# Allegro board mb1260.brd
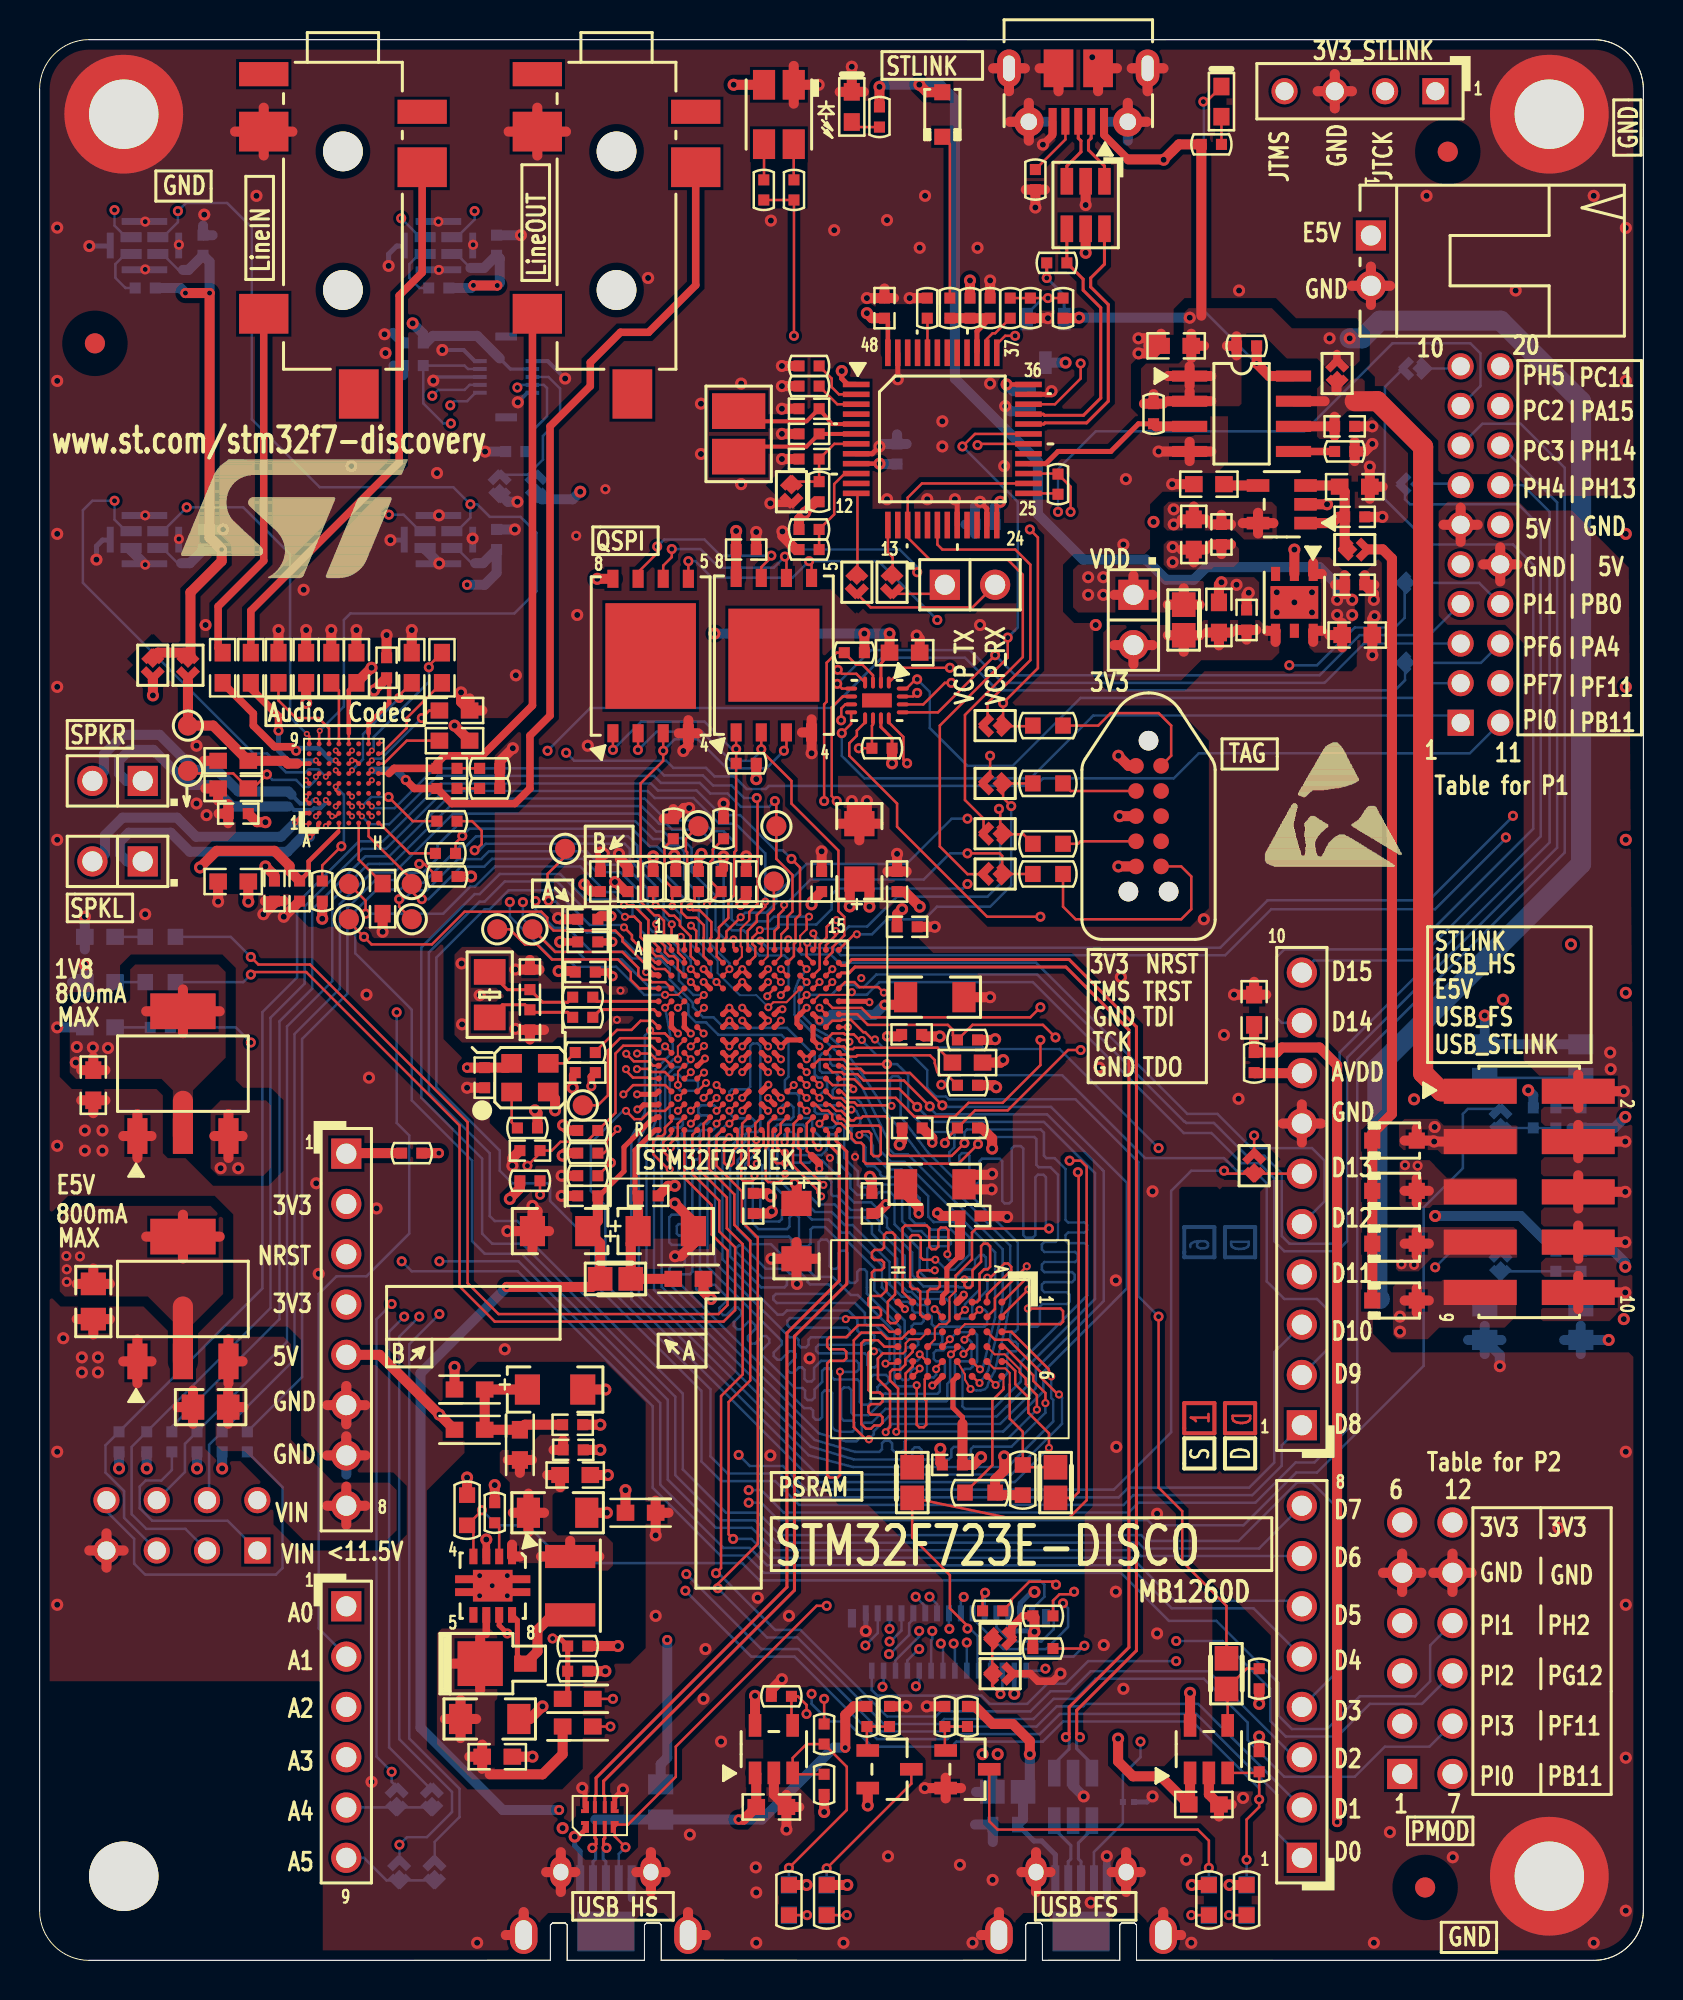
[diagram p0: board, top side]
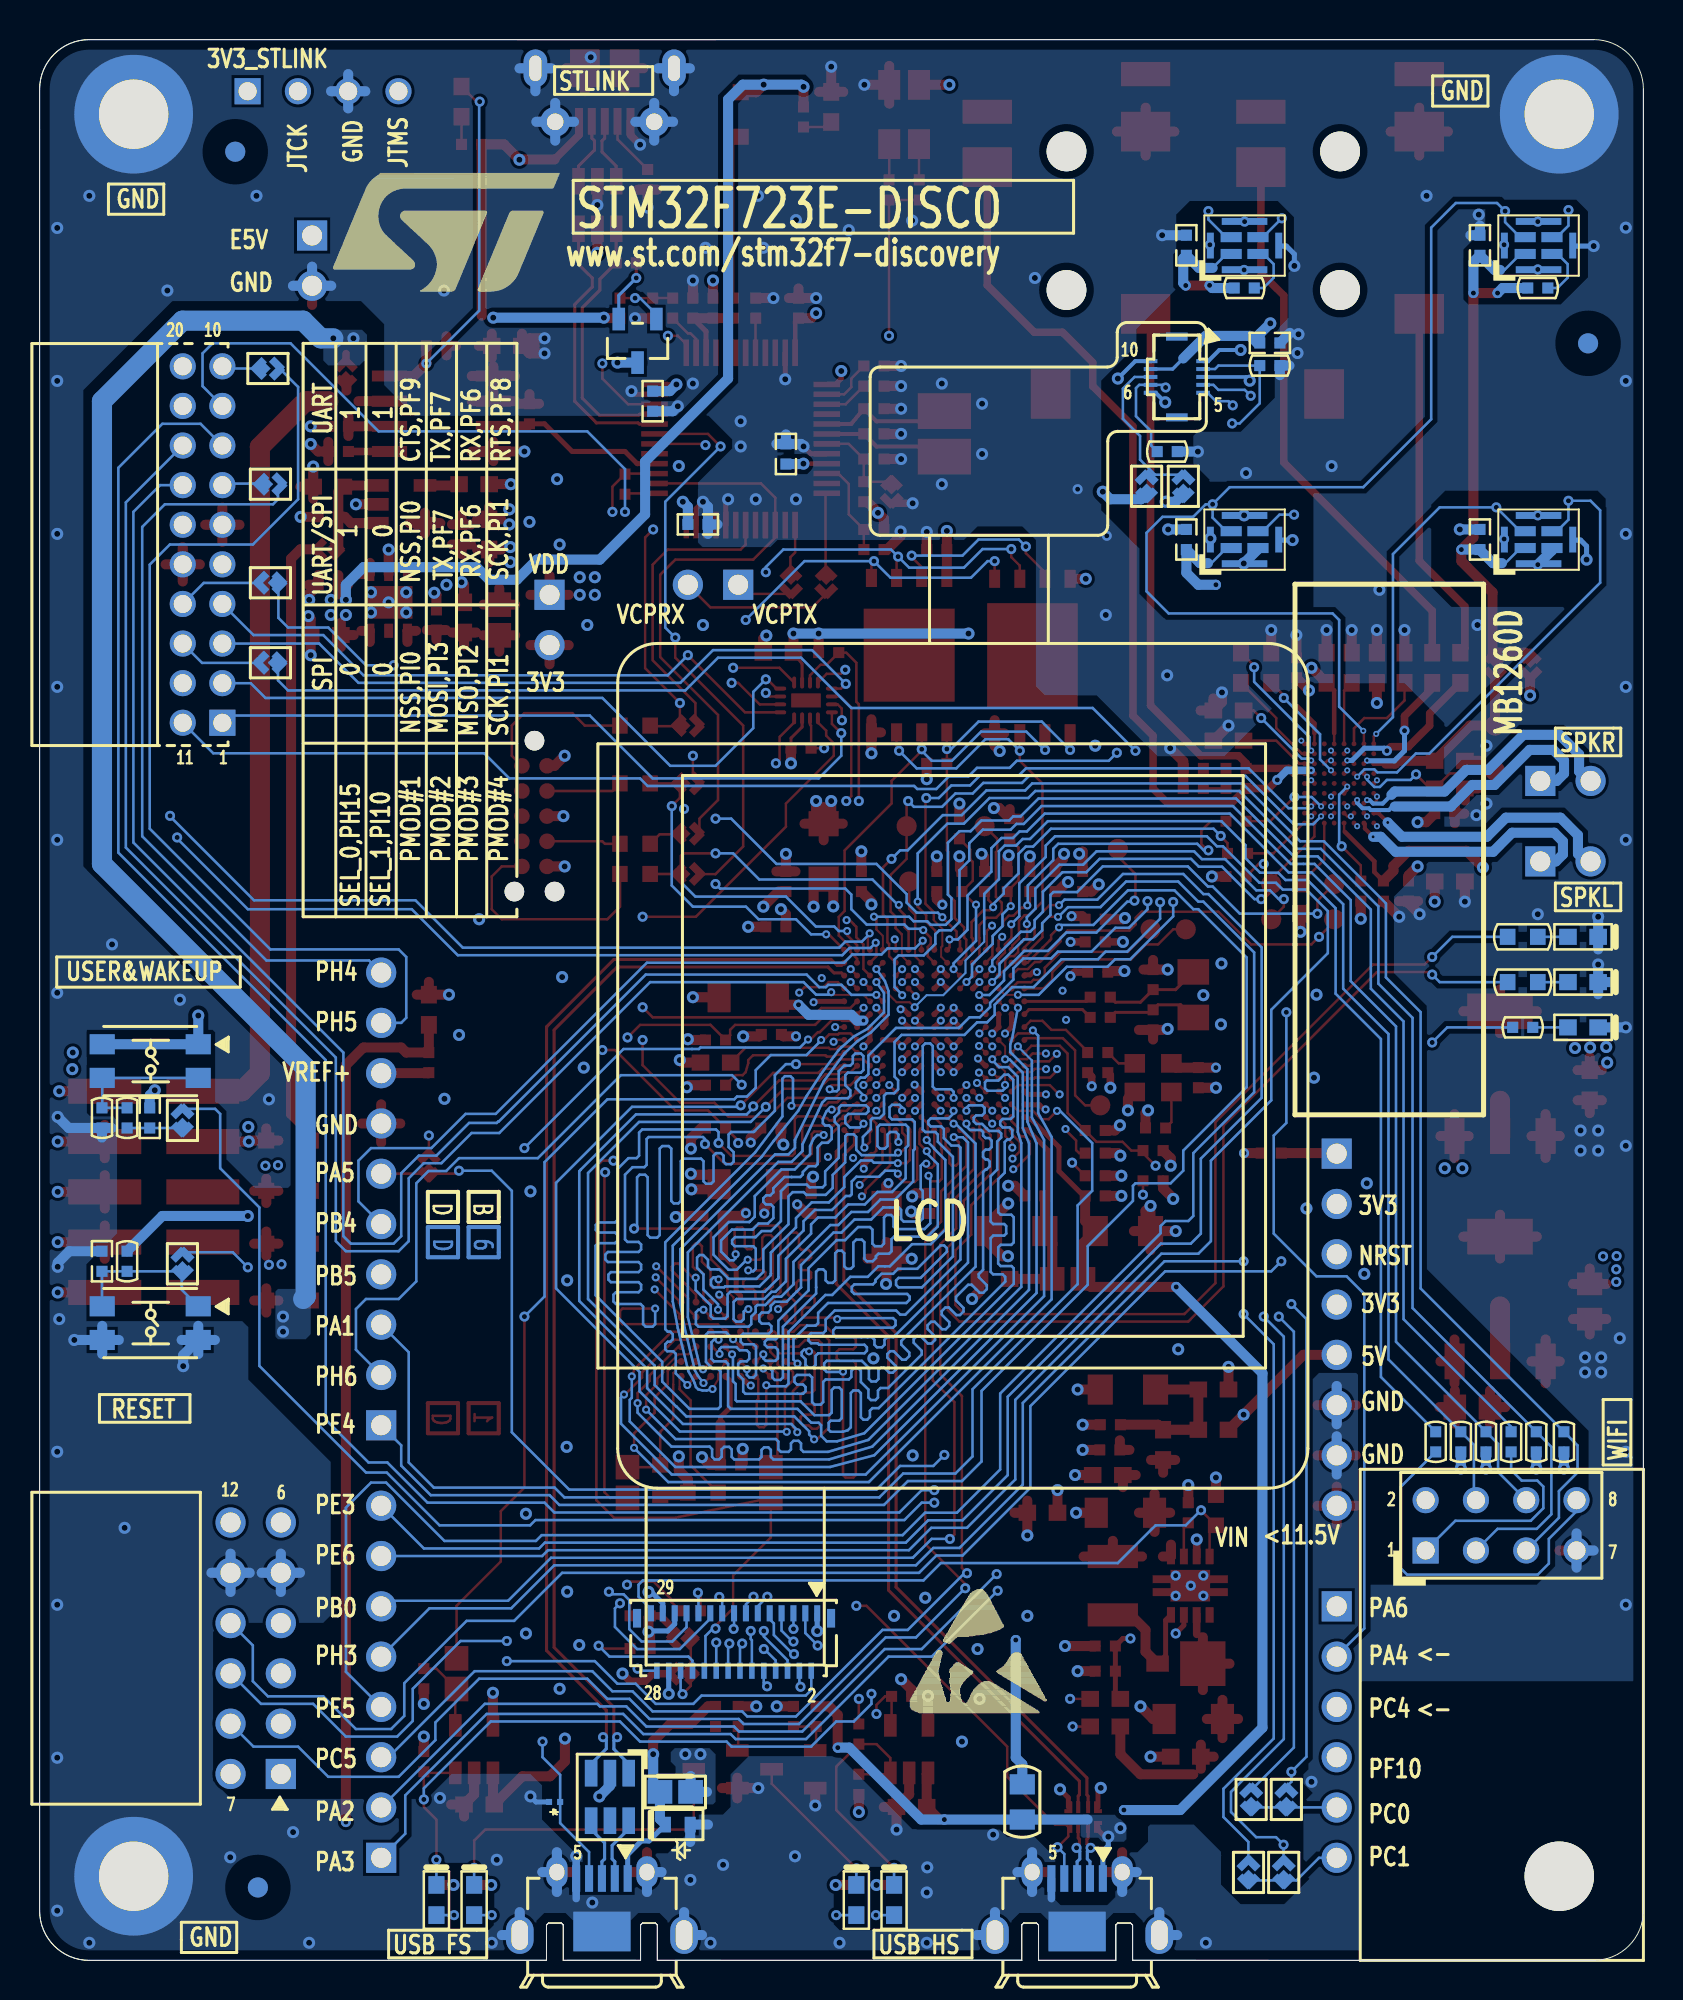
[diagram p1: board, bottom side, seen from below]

Outline 81 x 97 mm; copper layers: TOP, L2_GND, L3_VCC, L4_SIG, L5_GND, BOTTOM. Coordinates in mm from the lower left corner of the outline.
Outline path: 0,94.49 0,90.31 ; 0,94.49 arc(0.74,96.26) 2.51,97 ; 0,94.49 0,90.31 ; 0,90.31 0,2.51 ; 0,90.31 0,2.51 ; 2.51,97 78.49,97 ; 2.51,97 78.49,97 ; 0,2.51 arc(0.74,0.74) 2.51,0 ; 78.49,97 arc(80.27,96.26) 81,94.49 ; 78.49,97 arc(80.27,96.26) 81,94.49 ; 2.51,0 25.8,0 ; 2.51,0 25.8,0 ; 25.8,0 18.95,0 ; 25.8,0 25.8,1.79 ; 25.8,0 25.8,1.79 ; 25.8,1.79 25.9,1.89 ; 25.8,1.79 25.9,1.89 ; 25.9,1.89 26.55,1.89 ; 25.9,1.89 26.55,1.89 ; 26.55,1.89 26.65,1.79 ; 26.55,1.89 26.65,1.79 ; 26.65,1.79 26.65,0 ; 26.65,1.79 26.65,0 ; 26.65,0 30.55,0 ; 26.65,0 30.55,0 ; 30.55,0 30.55,1.79 ; 30.55,0 30.55,1.79 ; 30.55,1.79 30.65,1.89 ; 30.55,1.79 30.65,1.89 ; 30.65,1.89 31.3,1.89 ; 30.65,1.89 31.3,1.89 ; 31.3,1.89 31.4,1.79 ; 31.3,1.89 31.4,1.79 ; 31.4,1.79 31.4,0 ; 31.4,1.79 31.4,0 ; 31.4,0 34.57,0 ; 31.4,0 48.9,0 ; 31.4,0 49.8,0 ; 31.4,0 49.8,0 ; 49.8,0 49.8,1.79 ; 49.8,0 49.8,1.79 ; 49.8,1.79 49.9,1.89 ; 49.8,1.79 49.9,1.89 ; 49.9,1.89 50.55,1.89 ; 49.9,1.89 50.55,1.89 ; 50.55,1.89 50.65,1.79 ; 50.55,1.89 50.65,1.79 ; 50.65,1.79 50.65,0 ; 50.65,1.79 50.65,0 ; 50.65,0 54.55,0 ; 50.65,0 54.55,0 ; 54.55,0 54.55,1.79 ; 54.55,0 54.55,1.79 ; 50.93,0 54.36,0 ; 54.55,1.79 54.65,1.89 ; 54.55,1.79 54.65,1.89 ; 54.65,1.89 55.3,1.89 ; 54.65,1.89 55.3,1.89 ; 55.3,1.89 55.4,1.79 ; 55.3,1.89 55.4,1.79 ; 55.4,1.79 55.4,0 ; 55.4,1.79 55.4,0 ; 55.4,0 58.57,0 ; 55.4,0 78.49,0 ; 55.4,0 78.49,0 ; 78.49,0 arc(80.27,0.74) 81,2.51 ; 78.49,0 arc(80.27,0.74) 81,2.51 ; 81,94.49 81,92.47 ; 81,94.49 81,92.47 ; 81,92.47 81,2.51 ; 81,92.47 81,2.51

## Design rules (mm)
net group 5V_USB_HS: nets 5V_USB_HS USB_OTGHS_VBUS
net group ARD_D5: nets ARD_D5 STMOD+_TIM3_CH3
net group ARD_D14: nets ARD_D14 STMOD+_I2C2_SDA
net group DIFFPAIR1: nets NETCN7_1 NETCN7_2
net group DIFFPAIR2: nets NETCN10_1 NETCN10_2
net group LCD-RS_A0: nets LCD-RS_A0 PSRAM_A0
net group LCD_PSRAM_NWE: nets LCD_PSRAM_NWE NETR64_2
net group NETB1_2: nets NETB1_2 NETC86_2
net group NETC9_2: nets NETC9_2 NETD2_2
net group NETC18_1: nets NETC18_1 NETC18_2
net group NETC25_1: nets NETC25_1 NETC25_2
net group NETC27_1: nets NETC27_1 NETC27_2
net group NETC30_1: nets NETC30_1 NETC30_2
net group NETC32_1: nets NETC32_1 NETC32_2
net group NETC48_2: nets NETC48_2 PC14-OSC32_IN
net group NETC51_2: nets NETC51_2 PC15-OSC32_OUT
net group NETCN14_1: nets NETCN14_1 WIFI_RX
net group NETCN14_8: nets NETCN14_8 WIFI_TX
net group NETLD5_1: nets NETLD5_1 SYS_LD_USER1
net group NETLD6_1: nets NETLD6_1 SYS_LD_USER2
net group NETLD7_2: nets NETLD7_2 USB_OTGHS_OVCR
net group NETR10_1: nets NETR10_1 USB_STLK_P
net group NETR35_2: nets NETR35_2 SAI2_I2C1_SDA
net group NETR39_2: nets NETR39_2 SAI2_I2C1_SCL
net group NETR63_1: nets NETR63_1 PSRAM_NE1
net group NETR72_2: nets NETR72_2 USB_OTGFS_PPWR_EN
net group NETR76_2: nets NETR76_2 USB_OTGFS_VBUS
net group OSC_25M: nets OSC_25M PH0-OSCIN
net group STLINK_RX: nets STLINK_RX VCP_TX
net group STLINK_TX: nets STLINK_TX VCP_RX
net group SYS_STLINK_JTMS: nets SYS_STLINK_JTMS TAG_SWDIO
net group T_JTMS: nets T_JTMS T_SWDIO_IN
net group USB_OTGFS: nets USB_OTGFS_N USB_OTGFS_P
net group USB_OTGFS_CN: nets USB_OTGFS_CN_N USB_OTGFS_CN_P
net group USB_OTGHS: nets USB_OTGHS_N USB_OTGHS_P
net group USB_OTGHS_CN: nets USB_OTGHS_CN_N USB_OTGHS_CN_P
net group USB_STLK_CN: nets USB_STLK_CN_N USB_STLK_CN_P
net group 3V3_ST_LINK: nets AIN_1 NETD1_2 PWR_EXT STM_RST
net group 5V: nets NETLD2_1
net group 5V_ST_LINK: nets NETLD3_1 NETLD3_2 NETR7_1 PWR_ENN USB_RENUMN
net group ARD_A5: nets ARD_A5 ARD_D15 NETCN15_6
net group ARD_D13: nets ARD_D13 NETLD1_1 NETR12_2
net group BLGND: nets LEDK NETC67_1 NETL7_2 NETR67_2
net group DATA: nets NETR19_2
net group DIFFPAIR0: nets USB_STLK_N
net group DMIC_VDD: nets DMIC_VDD NETR85_1 NETR86_1
net group E5V: nets NETCN12_1
net group LED_STLINK: nets LED_STLINK NETLD4_2 NETLD4_3
net group NETB2_1: nets NETB2_1 NRST TAG_NRST
net group NETCN11_8: nets NETCN11_8 VDDA VREF+
net group SYS_STLINK_JTCK: nets SYS_STLINK_JTCK T_JTCK TAG_SWCLK
net group SYS_STLINK_JTDO-SWO: nets SYS_STLINK_JTDO-SWO T_SWO TAG_SWO

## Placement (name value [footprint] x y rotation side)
B1  SW-PUSH-CMS_EVQP2_BLUE  [TACT_4SM_3R5X5R5]  75.41 45.42 90 bottom
B2  SW-PUSH-CMS_EVQP2_BLACK  [TACT_4SM_3R5X5R5]  75.41 32.18 90 bottom
C1  100nF  [0402C]  42.67 83.44 90 top
C2  100nF  [0402C]  18.87 81.68 180 bottom
C3  1uF  [0603C]  57.4 81.53 0 top
C4  10pF  [0402C]  38.86 78.36 0 top
C5  100nF  [0402C]  65.91 77.47 180 top
C6  10pF  [0402C]  38.86 77.09 0 top
C7  100nF  [0402C]  38.86 75.82 0 top
C8  10nF_X7R_10%_0603  [0603C]  59.05 74.55 0 top
C9  1uF  [0603C]  66.42 74.42 180 top
C10  100nF  [0402C]  66.42 72.9 180 top
C11  1uF  [0603C]  58.29 72.01 90 top
C12  100nF  [0402C]  59.69 72.01 90 top
C13  100nF  [0402C]  35.69 71.25 180 top
C14  100nF  [0402C]  66.42 69.47 180 top
C15  1uF  [0603C]  59.56 67.82 270 top
C16  100nF  [0402C]  60.96 67.69 270 top
C17  1uF  [0603C]  66.55 66.93 180 top
C18  1uF  [0603C]  10.67 65.28 90 top
C19  4.7uF  [0603C]  12.06 65.28 270 top
C20  4.7uF  [0603C]  13.46 65.28 90 top
C21  4.7uF  [0603C]  14.73 65.28 90 top
C22  4.7uF  [0603C]  16 65.28 90 top
C23  100nF  [0402C]  17.53 65.28 90 top
C24  1uF  [0603C]  18.8 65.28 90 top
C25  2.2uF_X5R_10%_0603  [0603C]  20.32 65.28 90 top
C26  2.2uF_X5R_10%_0603  [0603C]  20.95 63.12 0 top
C27  1uF  [0603C]  9.25 65.28 90 top
C28  2.2uF_X5R_10%_0603  [0603C]  20.95 61.59 0 top
C29  4.7uF  [0603C]  9.78 60.58 0 top
C30  100nF  [0402C]  20.57 60.2 0 top
C31  4.7uF  [0603C]  9.78 59.18 0 top
C32  100nF  [0402C]  20.57 59.18 0 top
C33  100nF  [0402C]  10.03 57.91 180 top
C34  4.7uF  [TAN-A]  41.4 56.01 270 top
C35  1uF  [0603C]  9.78 54.48 0 top
C36  100nF  [0402C]  28.32 54.48 270 top
C37  100nF  [0402C]  29.72 54.48 270 top
C38  100nF  [0402C]  35.69 54.48 270 top
C39  100nF  [0402C]  39.5 54.48 270 top
C40  100nF  [0402C]  43.31 54.48 270 top
C41  100nF  [0402C]  11.86 54 270 top
C42  100nF  [0402C]  13.13 54 270 top
C43  1uF  [0603C]  17.32 53.62 90 top
C44  100nF  [0402C]  27.69 52.58 0 top
C45  100nF  [0402C]  43.81 52.2 180 top
C46  100nF  [0402C]  27.69 51.44 0 top
C47  100nF  [0402C]  27.56 49.91 0 top
C48  4.7pF_NPO_-+0.25pF_0402  [0402C]  24.77 49.53 270 top
C49  2.2uF  [1206C]  45.21 48.64 180 top
C50  1uF  [0603C]  61.34 48.01 270 top
C51  4.7pF_NPO_-+0.25pF_0402  [0402C]  24.77 47.5 90 top
C52  100nF  [0402C]  44.04 46.76 180 top
C53  100nF  [0402C]  27.56 44.83 0 top
C54  2.2uF_X5R_10%_0603  [0603C]  46.86 45.34 0 top
C55  100nF  [0402C]  22.48 44.58 90 top
C56  100nF  [0402C]  44.07 42.04 180 top
C57  10uF  [0603C]  2.71 44.2 90 top
C58  2.2uF  [1206C]  45.21 39.19 180 top
C59  100nF  [0402C]  27.69 38.61 0 top
C60  100nF  [0402C]  30.73 38.61 180 top
C61  100nF  [0402C]  36.04 38.23 90 top
C62  100nF  [0402C]  42.04 38.23 90 top
C63  100nF  [0402C]  46.99 37.59 180 top
C64  1uF  [TAN-A]  26.29 36.83 0 top
C65  1uF  [TAN-A]  31.62 36.83 180 top
C66  4.7uF  [TAN-A]  38.23 36.83 90 top
C67  10uF_POL_10%_TANA  [TAN-A]  26.04 28.83 180 top
C68  10uF  [0805C]  2.71 33.27 90 top
C69  100nF  [0402C]  26.92 27.05 180 top
C70  100nF  [0402C]  26.95 25.78 180 top
C71  100nF  [0402C]  46.1 25.02 0 top
C72  10nF_X7R_10%_0603  [0603C]  27.05 24.51 180 top
C73  4.7uF_X7R_10%_1206  [1206C]  26.16 22.61 180 top
C74  10uF  [0805C]  8.64 27.94 0 top
C75  4.7uF_X7R_10%_1206  [1206C]  22.73 12.19 180 top
C76  10nF_X7R_10%_0603  [0603C]  23.11 10.29 180 top
C77  4.7uF  [0603C]  58.8 7.87 0 top
C78  4.7uF  [0603C]  36.96 7.75 0 top
C79  100nF  [0402C]  23.08 86.61 90 bottom
C80  100nF  [0402C]  8.26 86.61 90 bottom
C81  100nF  [0402C]  50.04 78.74 90 bottom
C82  100nF  [0402C]  43.31 76.07 270 bottom
C83  100nF  [0402C]  47.75 72.52 0 bottom
C84  100nF  [0402C]  23.08 71.75 90 bottom
C85  100nF  [0402C]  8.26 71.75 90 bottom
C86  100nF  [0402C]  75.44 42.55 270 bottom
C87  100nF  [0402C]  77.85 35.31 270 bottom
C92  1uF  [0603C]  43.69 66.04 0 top
C93  100nF  [0402C]  24.77 40.89 0 top
CN1  1050170001  [MICRO_USB_B_105017]  52.46 92.95 180 top
CN2  Header 4  [HDR_1X4_2R54]  70.5 94.39 180 top
CN3  WF25402-06421  [HDR_1X2_2R54_RA_11R35]  67.24 87.11 90 top
CN4  PJ3028B-3_BE_3PINS  [PJ3028B]  15.32 91.35 270 top
CN5  PJ3028B-3_GR_3PINS  [PJ3028B]  29.14 91.35 270 top
CN6  JP2  [SIP2]  45.72 69.47 0 top
CN7  JP2  [SIP2]  5.21 59.56 180 top
CN8  Header M Straight 5x2H TSM  [TSM-105-01-S-DV]  75.23 38.81 270 top
CN9  -  [TC2050-IDC-NL]  56.01 57.78 270 top
CN10  JP2  [SIP2]  5.21 55.5 180 top
CN11  BL 1-10 G  [HDR_1X10_2R54_W]  63.75 27.02 90 top
CN12  BL 1-8 G  [HDR_1X8_2R54_W]  15.49 40.74 270 top
CN13  BL 1-8 G  [HDR_1X8_2R54_W]  63.75 5.18 90 top
CN14  Header F Straight 4x2H  [HDR_2X4_2R54]  11 20.7 180 bottom
CN15  BL 1-6 G  [HDR_1X6_2R54_W]  15.49 17.88 270 top
CN16  DF37NB-10DS-0.4V (5x)  [DF37NB-10DS-0R4V]  23.56 79.96 90 bottom
CN17  FH26-29S-0.3SHW  [FH26-29S-0R3SHW]  45.93 16.08 0 bottom
CN18  475900001  [MOLEX_47590001]  52.6 4.14 180 bottom
CN19  475900001  [MOLEX_47590001]  28.6 4.14 180 bottom
D1  BAT60JFILM  [SOD-323]  45.59 93.22 90 top
D2  BAT60JFILM  [SOD-323]  68.43 33.32 0 top
D3  BAT60JFILM  [SOD-323]  68.43 36.2 0 top
D4  BAT60JFILM  [SOD-323]  68.43 38.86 0 top
D5  BAT60JFILM  [SOD-323]  68.43 41.4 0 top
H1  POSITION HOLE C6D3R5  [HOLE_C6D3R5]  76.25 93.23 0 top
H2  POSITION HOLE C6D3R5  [HOLE_C6D3R5]  4.25 93.23 0 top
H4  POSITION HOLE C6D3R5  [HOLE_C6D3R5]  76.25 4.25 0 top
JP1  JP2  [SIP2]  55.24 68.96 270 top
L1  FCM1608KF-601T03  [0603L]  32.77 34.42 180 top
L2  FCM1608KF-601T03  [0603L]  21.72 28.83 0 top
L3  FCM1608KF-601T03  [0603L]  21.72 26.8 0 top
L4  FCM1608KF-601T03  [0603L]  24.26 26.04 270 top
L5  FCM1608KF-601T03  [0603L]  30.35 22.61 180 top
L6  4.7uH 1A 30%  [1210L]  26.8 18.92 270 top
L7  FCM1608KF-601T03  [0603L]  27.18 13.21 180 top
L8  FCM1608KF-601T03  [0603L]  27.18 11.81 0 top
LD1  LED blue  [0603D]  3.05 47.12 180 bottom
LD2  LED red  [0603D]  41.02 93.6 90 top
LD3  LED red  [0603D]  59.69 93.87 90 top
LD4  LD_BICOLOR_CMS  [LED2_3528]  37.34 93.22 180 top
LD5  LED red  [0603D]  3.05 51.69 180 bottom
LD6  LED green  [0603D]  3.05 49.4 180 bottom
LD7  LED red  [0603D]  37.85 3.05 90 bottom
LD8  LED green  [0603D]  39.75 3.05 90 bottom
LD9  LED green  [0603D]  59.05 3.05 90 bottom
LD10  LED red  [0603D]  60.96 3.05 90 bottom
NOREF  -  []  450.6 -120.4 0 top
NOREF#2  -  []  13.59 -41.66 0 top
NOREF#3  -  []  15.49 17.88 90 top
NOREF#4  -  []  4.62 72.17 90 top
NOREF#5  -  []  2.51 0 90 top
NOREF#6  -  []  4.7 228.5 0 top
NOREF#7  -  []  283.34 118.87 0 top
NOREF#8  -  []  4.25 4.25 90 top
NOREF#9  -  []  -7.62 0 0 top
NOREF#10  -  []  4.25 4.25 0 top
NOREF#11  -  []  322.2 176.15 0 top
NOREF#12  -  [unnamed#2]  71.12 91.34 0 top
NOREF#13  -  [unnamed#2]  2.79 81.66 0 top
NOREF#14  -  []  4.62 87.02 0 top
NOREF#15  -  []  15.49 5.18 0 top
NOREF#16  -  []  63.75 22.96 90 top
NOREF#17  -  [unnamed#2]  69.98 3.68 0 top
NOREF#18  -  []  0 2.51 0 top
NOREF#19  -  [unnamed#2]  4.25 4.25 0 top
NOREF#20  -  []  76.25 4.25 0 top
NOREF#21  -  []  78.49 0 90 top
NOREF#22  Value  []  34.37 45.18 270 bottom
NOREF#23  -  [unnamed#2]  69.98 3.68 180 bottom
NOREF#24  -  [unnamed#2]  71.12 91.34 180 bottom
NOREF#25  -  [unnamed#2]  2.79 81.66 180 bottom
NOREF#26  Value  []  -60.71 -15.54 270 bottom
P1  -  [SQT-110-01-F-D-RA]  72.77 71.5 270 bottom
P2  -  [SSW-106-02-F-D-RA]  68.82 9.41 270 bottom
R1  1K  [0402R]  42.42 93.09 270 top
R2  1K  [0402R]  59.18 91.71 180 top
R3  100K_1%_0402  [0402R]  44.83 83.44 270 top
R4  2K7  [0402R]  45.97 83.44 90 top
R5  0  [0402R]  46.99 83.44 90 top
R6  4K7_1%_0402  [0402R]  48.01 83.44 270 top
R7  100  [0402R]  49.02 83.44 270 top
R8  36K  [0402R]  50.04 83.44 90 top
R9  100K_1%_0402  [0402R]  50.29 89.93 90 top
R10  1K5  [0402R]  51.37 85.72 0 top
R11  10K  [0402R]  51.69 83.44 90 top
R12  680_1%_0402  [0402R]  6.1 47.12 0 bottom
R13  330  [0402R]  36.58 89.41 90 top
R14  330  [0402R]  38.1 89.41 90 top
R15  100K_1%_0402  [0402R]  60.96 81.53 180 top
R16  47K_1%_0402  [0402R]  37.47 13.34 0 top
R17  10K  [0402R]  38.86 80.52 0 top
R18  100K_1%_0402  [0402R]  24.05 76.19 0 bottom
R19  10K  [0402R]  38.86 79.5 0 top
R20  10K  [0402R]  56.26 78.11 90 top
R21  100K_1%_0402  [0402R]  18.87 80.54 0 bottom
R22  2K2  [0402R]  65.91 76.2 0 top
R23  100  [0402R]  51.44 74.55 270 top
R24  100K_1%_0402  [0402R]  39.37 74.17 270 top
R25  4K7_1%_0402  [0402R]  38.86 72.26 0 top
R26  4K7_1%_0402  [0402R]  38.86 71.25 0 top
R27  0_5%_0603  [0603R-GS]  57.78 67.69 270 top
R28  22R  [R0603]  50.93 62.36 180 top
R29  10K  [0402R]  42.55 61.21 180 top
R30  10K  [0402R]  35.69 60.45 0 top
R31  20  [0402R]  22.73 60.2 0 top
R32  22R  [R0603]  50.93 59.44 180 top
R33  20  [0402R]  22.73 59.18 0 top
R35  0  [0402R]  20.57 57.53 180 top
R36  10K  [0402R]  32 57.15 270 top
R37  10K  [0402R]  34.54 57.15 270 top
R38  22R  [R0603]  50.93 56.39 180 top
R39  0  [0402R]  20.5 55.91 180 top
R40  22R  [R0603]  50.93 54.86 180 top
R41  10K  [0402R]  20.57 54.74 180 top
R42  2K7  [0402R]  30.99 54.48 270 top
R43  10K  [0402R]  32.13 54.48 270 top
R44  2K7  [0402R]  33.27 54.48 270 top
R45  10K  [0402R]  34.42 54.48 270 top
R46  10K  [0402R]  14.27 54 270 top
R47  1K_1%_0603  [0603R]  6.1 51.69 180 bottom
R48  510_1%_0603  [0603R]  6.1 49.4 180 bottom
R49  0  [0402R]  27.43 48.64 0 top
R50  0  [0402R]  27.43 47.62 0 top
R51  100  [0402R]  27.56 45.85 0 top
R52  2K7  [0402R]  46.86 46.48 180 top
R53  0  [0402R]  61.34 45.34 90 top
R54  3K  [0402R]  46.86 44.2 0 top
R55  10K  [0402R]  24.64 42.04 180 top
R56  2K7  [0402R]  46.86 42.04 0 top
R57  10K  [0402R]  27.69 41.91 180 top
R58  1K  [0402R]  18.8 40.77 0 top
R59  2K7  [0402R]  24.77 39.37 180 top
R60  2K7  [0402R]  27.69 40.77 180 top
R61  10K  [0402R]  27.69 39.62 0 top
R62  0_5%_0603  [0603R-GS]  29.08 34.42 0 top
R63  10K_1%_0603  [0603R]  49.66 24.26 270 top
R64  0_5%_0603  [0603R-GS]  44.07 24.13 90 top
R65  0_5%_0603  [0603R-GS]  51.31 24.13 90 top
R66  10_1%_0603  [0603R]  21.59 22.73 270 top
R67  100K_1%_0402  [0402R]  22.99 22.61 270 top
R68  100K_1%_0402  [0402R]  50.67 17.4 0 top
R69  100K_1%_0402  [0402R]  27.18 15.88 180 top
R70  100K_1%_0402  [0402R]  50.67 15.75 0 top
R71  100K_1%_0402  [0402R]  27.18 14.61 180 top
R72  0_5%_0603  [0603R-GS]  59.94 14.48 270 top
R73  47K_1%_0402  [0402R]  61.59 14.22 270 top
R74  47K_1%_0402  [0402R]  41.78 12.32 90 top
R75  100K_1%_0402  [0402R]  42.93 12.32 90 top
R76  10K  [0402R]  45.72 12.32 270 top
R77  47K_1%_0402  [0402R]  46.86 12.32 90 top
R78  0  [0402R]  39.62 11.43 90 top
R79  47K_1%_0402  [0402R]  61.59 10.03 90 top
R80  3K3  [0402R]  39.62 8.89 90 top
R81  620_1%_0603  [0603R]  37.85 3.05 270 top
R82  330_1%_0603  [0603R]  39.75 3.05 90 top
R83  330_1%_0603  [0603R]  59.05 3.05 90 top
R84  620_1%_0603  [0603R]  60.96 3.05 90 top
R85  10K  [0402R]  20.16 84.45 0 bottom
R86  10K  [0402R]  5.33 84.45 0 bottom
R89  10K  [0402R]  77.85 42.55 90 bottom
R90  10K  [0402R]  76.58 42.55 90 bottom
R91  10K  [0402R]  76.58 35.31 90 bottom
R92  1K  [0402R]  6.68 26.19 270 bottom
R93  10K  [0402R]  5.41 26.19 90 bottom
R94  10K  [0402R]  9.22 26.19 90 bottom
R95  10K  [0402R]  7.95 26.19 90 bottom
R96  10K  [0402R]  4.01 26.19 90 bottom
R97  1K  [0402R]  10.49 26.19 90 bottom
R98  0_5%_0805  [0805R]  31.37 8 270 bottom
R99  0_5%_0603  [0603R-GS]  48.9 8.51 180 bottom
R100  10K_1%_0603  [0603R]  47.5 23.62 0 top
R101  0  [0402R]  48.13 17.65 180 top
R102  10K  [0402R]  41.15 66.04 0 top
SB1  Solder Bridge ON  [JP2_SMD]  5.71 65.41 90 top
SB2  Solder Bridge OFF  [JP2_SMD]  23.24 74.44 270 bottom
SB3  Solder Bridge OFF  [JP2_SMD]  65.53 80.14 270 top
SB4  Solder Bridge ON  [JP2_SMD]  25.09 74.44 270 bottom
SB5  Solder Bridge OFF  [JP2_SMD]  7.49 65.41 90 top
SB6  Solder Bridge OFF  [JP2_SMD]  37.97 74.17 90 top
SB7  Solder Bridge ON  [JP2_SMD]  66.42 71.25 180 top
SB8  Solder Bridge ON  [JP2_SMD]  41.27 69.6 90 top
SB9  Solder Bridge ON  [JP2_SMD]  43.05 69.6 90 top
SB10  Solder Bridge ON  [JP2_SMD]  48.26 62.36 0 top
SB11  Solder Bridge ON  [JP2_SMD]  48.26 59.44 0 top
SB12  Solder Bridge ON  [JP2_SMD]  48.26 56.9 0 top
SB13  Solder Bridge ON  [JP2_SMD]  48.26 54.86 0 top
SB14  Solder Bridge ON  [JP2_SMD]  61.34 40.13 270 top
SB15  Solder Bridge ON  [JP2_SMD]  48.51 16.26 180 top
SB16  Solder Bridge OFF  [JP2_SMD]  48.51 14.48 180 top
SB25  Solder Bridge ON  [JP2_SMD]  69.34 74.55 0 bottom
SB27  Solder Bridge ON  [JP2_SMD]  69.47 80.39 0 bottom
SB28  Solder Bridge ON  [JP2_SMD]  69.34 65.53 180 bottom
SB29  Solder Bridge ON  [JP2_SMD]  69.34 69.57 180 bottom
SB33  Solder Bridge ON  [JP2_SMD]  73.79 42.42 270 bottom
SB34  Solder Bridge ON  [JP2_SMD]  73.79 35.18 270 bottom
SB35  Solder Bridge ON  [JP2_SMD]  19.81 8.13 270 bottom
SB36  Solder Bridge OFF  [JP2_SMD]  18.03 8.13 270 bottom
SB37  Solder Bridge ON  [JP2_SMD]  19.94 4.44 270 bottom
SB38  Solder Bridge OFF  [JP2_SMD]  18.17 4.44 270 bottom
T1  9013-SOT23  [SOT-23]  42.93 9.65 180 top
T2  9013-SOT23  [SOT-23]  46.86 9.65 180 top
T3  9013-SOT23  [SOT-23]  50.8 81.79 90 bottom
TP1  TP  [TP_C40]  7.49 62.36 180 top
TP2  TP  [TP_C40]  7.49 60.07 180 top
TP3  TP  [TP_C40]  33.27 57.28 0 top
TP4  TP  [TP_C40]  37.21 57.28 0 top
TP5  TP  [TP_C40]  37.08 54.48 0 top
TP6  TP  [TP_C40]  15.62 54.36 0 top
TP7  TP  [TP_C40]  18.8 54.36 0 top
TP8  TP  [TP_C40]  26.54 56.13 0 top
TP11  TP  [TP_C40]  15.62 52.58 0 top
TP12  TP  [TP_C40]  18.8 52.58 0 top
TP13  TP  [TP_C40]  23.11 52.07 0 top
TP14  TP  [TP_C40]  24.89 52.07 0 top
TP15  TP  [TP_C40]  27.43 43.18 0 top
U1  ST890CDR  [SOIC8_1R27_4R9X6]  60.71 78.11 270 top
U2  STM32F103CBT6  [LQFP48_0R5_9X9]  45.59 76.83 0 top
U3  LD3985M33R  [SOT-23-5L]  62.74 73.53 90 top
U4  LD39050PU33R  [DFN6_0R95_3X3]  63.37 68.58 180 top
U5  MX25L51245G (MACRONIX)  [SON8_1R27_6X8]  37.08 65.91 0 top
U6  N25Q512A13GF840E (MICRON)  [DFN8_1R27_6X8_TP4R6X5R3]  30.86 65.87 0 top
U7  WM8994ECS_R  [BGA72_0R5_4R5X4]  15.37 59.44 90 top
U8  STM32F723IEK  [BGA176_0R65_10X10]  35.81 46.48 0 top
U9  LD1117S18TR  [SOT-223]  7.24 44.78 270 top
U10  IS66WV51216EBLL-55BLI  [FBGA48_0R75_6X8]  45.97 31.37 270 top
U11  LD1117S50TR  [SOT-223]  7.24 33.4 270 top
U12  STLD40DPUR  [SON8_0R65_3X3]  22.89 18.92 180 top
U13  STMPS2151STR  [SOT23-5]  37.08 10.67 0 top
U14  STMPS2141STR  [SOT23-5]  59.05 10.67 0 top
U15  ECMF02-4CMX8  [QFN8_0R5_2R5X1R2]  28.3 7.24 0 top
U16  MP34DT01  [MP34DT01TR]  20.14 86.6 90 bottom
U17  MP34DT01  [MP34DT01TR]  5.29 86.6 90 bottom
U18  MP34DT01  [MP34DT01TR]  20.14 71.75 90 bottom
U19  MP34DT01  [MP34DT01TR]  5.29 71.75 90 bottom
U20  STG3692QTR  [QFN16_0R4_2R5X1R7]  42.29 63.63 180 top
U21  USBLC6-2SC6  [SOT23-6]  52.83 88.65 180 top
U22  USBLC6-2SC6  [SOT23-6]  52.2 8.26 0 bottom
U23  ESDALC6V1-1U2  [D0201_21]  54.99 8 0 bottom
U24  ESDA7P60-1U1M  [DO_2SM_1R6X1_21]  48.77 6.86 180 bottom
X1  NX3225GD-8.00M  [XTAL_2SM_3R2X2R5_H1]  35.31 77.09 90 top
X2  NX3215SA-32.768K  [XTAL_2SM_3R2X1R5]  22.73 48.77 270 top
X3  NZ2520SB-25.00M  [OSC_4SM_2R5X2]  24.77 44.58 0 top
Z1  STPS1L40M  [DO-216AA]  24.54 14.99 0 top

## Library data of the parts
B1 B2 = TACT_4SM_3R5X5R5
C1 C4-C7 C10 C13 C14 C16 C23 C30 C32 C37 C40-C42 C44 C48 C51-C53 C56 C60 C63 C70 C71 C79-C81 C83-C87 C93 = 0402C: signal model: DEFAULT_CAPACITOR_100000pF_1_2
C2 = 0402C: signal model: DEFAULT_CAPACITOR_10pF_1_2
C3 C17-C19 C21 C22 C24-C26 C28 C29 C31 C35 C50 C54 C77 C78 = 0603C: signal model: DEFAULT_CAPACITOR_100000pF_1_2
C8 C20 = 0603C: signal model: DEFAULT_CAPACITOR_10000pF_1_2
C9 C57 C76 = 0603C: signal model: DEFAULT_CAPACITOR_4.7e+06pF_1_2
C11 = 0603C: signal model: DEFAULT_CAPACITOR_30pF_1_2
C12 C46 C61 = 0402C: signal model: DEFAULT_CAPACITOR_4.7e+06pF_1_2
C15 = 0603C: signal model: DEFAULT_CAPACITOR_20pF_1_2
C27 = 0603C: signal model: DEFAULT_CAPACITOR_1e+07pF_1_2
C33 = 0402C: signal model: DEFAULT_CAPACITOR_2.2e+06pF_2_1
C34 C65-C67 = TAN-A: signal model: DEFAULT_CAPACITOR_100000pF_1_2
C36 C55 = 0402C: signal model: DEFAULT_CAPACITOR_20pF_1_2
C38 C45 = 0402C: signal model: DEFAULT_CAPACITOR_2.2e+06pF_1_2
C39 = 0402C: signal model: DEFAULT_CAPACITOR_1e+07pF_1_2
C43 = 0603C: signal model: DEFAULT_CAPACITOR_2.2e+06pF_2_1
C47 = 0402C: signal model: DEFAULT_CAPACITOR_10000pF_1_2
C49 = 1206C: signal model: DEFAULT_CAPACITOR_4.7e+06pF_1_2
C58 C73 = 1206C: signal model: DEFAULT_CAPACITOR_100000pF_1_2
C59 C62 C69 = 0402C: signal model: DEFAULT_CAPACITOR_1e+06pF_1_2
C64 = TAN-A: signal model: DEFAULT_CAPACITOR_1e+07pF_1_2
C68 = 0805C: signal model: DEFAULT_CAPACITOR_100000pF_1_2
C72 C92 = 0603C: signal model: DEFAULT_CAPACITOR_1e+06pF_1_2
C74 = 0805C: signal model: DEFAULT_CAPACITOR_2.2e+06pF_2_1
C75 = 1206C: signal model: DEFAULT_CAPACITOR_10pF_1_2
C82 = 0402C: signal model: DEFAULT_CAPACITOR_6.7pF_1_2
CN1 = MICRO_USB_B_105017
CN2 = HDR_1X4_2R54
CN3 = HDR_1X2_2R54_RA_11R35
CN4 CN5 = PJ3028B
CN6 CN7 CN10 JP1 = SIP2
CN8 = TSM-105-01-S-DV
CN9 = TC2050-IDC-NL
CN11 = HDR_1X10_2R54_W
CN12 CN13 = HDR_1X8_2R54_W
CN14 = HDR_2X4_2R54
CN15 = HDR_1X6_2R54_W
CN16 = DF37NB-10DS-0R4V
CN17 = FH26-29S-0R3SHW
CN18 CN19 = MOLEX_47590001
D1-D5 = SOD-323
H1 H2 H4 = HOLE_C6D3R5
L1-L5 L7 L8 = 0603L
L6 = 1210L
LD1-LD3 LD5-LD10 = 0603D
LD4 = LED2_3528
P1 = SQT-110-01-F-D-RA
P2 = SSW-106-02-F-D-RA
R1 = 0402R: signal model: DEFAULT_RESISTOR_1000OHM_2_1
R2 R4 R23 R53 R58 R80 R96 R101 = 0402R: signal model: DEFAULT_RESISTOR_0.001OHM_1_2
R3 R5 R24 R25 R31 R42 R44 R52 R54 R59-R61 R67 R68 R70 R76 R77 R85 R90 R94 R97 = 0402R: signal model: DEFAULT_RESISTOR_33OHM_1_2
R6 = 0402R: signal model: DEFAULT_RESISTOR_680OHM_1_2
R7 = 0402R: signal model: DEFAULT_RESISTOR_4870OHM_1_2
R8 R35 R39 R46 = 0402R: signal model: DEFAULT_RESISTOR_50OHM_1_2
R9 = 0402R: signal model: DEFAULT_RESISTOR_47OHM_1_2
R10 = 0402R: signal model: DEFAULT_RESISTOR_1500OHM_1_2
R11-R13 R17 R18 R29 R30 R36 R37 R43 R45 R49-R51 R55-R57 R69 R102 = 0402R: signal model: DEFAULT_RESISTOR_10000OHM_1_2
R14 = 0402R: signal model: DEFAULT_RESISTOR_330OHM_2_1
R15 = 0402R: signal model: DEFAULT_RESISTOR_240OHM_1_2
R16 R21 R26 R74 R75 = 0402R
R19 = 0402R: signal model: DEFAULT_RESISTOR_10000OHM_2_1
R20 R33 R93 = 0402R: signal model: 0402R_33
R22 = 0402R: signal model: DEFAULT_RESISTOR_47000OHM_1_2
R27 R62 R65 R72 = 0603R-GS: signal model: DEFAULT_RESISTOR_10000OHM_1_2
R28 = R0603: signal model: DEFAULT_RESISTOR_0.001OHM_1_2
R32 = R0603: signal model: DEFAULT_RESISTOR_2200OHM_1_2
R38 R40 = R0603: signal model: DEFAULT_RESISTOR_680OHM_1_2
R41 R86 R92 = 0402R: signal model: DEFAULT_RESISTOR_220000OHM_1_2
R47 = 0603R: signal model: 0603R_33
R48 R63 R81 = 0603R: signal model: DEFAULT_RESISTOR_33OHM_1_2
R64 = 0603R-GS: signal model: DEFAULT_RESISTOR_33OHM_1_2
R66 R84 = 0603R: signal model: DEFAULT_RESISTOR_0.001OHM_1_2
R71 R79 R89 R91 = 0402R: signal model: 0603R_[n/a]
R73 = 0402R: signal model: DEFAULT_RESISTOR_820OHM_1_2
R78 = 0402R: signal model: DEFAULT_RESISTOR_100000OHM_1_2
R82 R100 = 0603R
R83 = 0603R: signal model: DEFAULT_RESISTOR_10000OHM_1_2
R95 = 0402R: signal model: 0603R_33
R98 = 0805R: signal model: DEFAULT_RESISTOR_0.001OHM_1_2
R99 = 0603R-GS
SB1 SB2 SB4 SB5 SB10 SB11 SB15 SB16 SB25 SB28 SB33 SB35 SB36 = JP2_SMD
SB3 SB6-SB9 SB12-SB14 SB27 SB29 SB34 SB37 SB38 = JP2_SMD: signal model: SB_0603_Closed
T1-T3 = SOT-23
TP1-TP8 TP11-TP15 = TP_C40
U1 = SOIC8_1R27_4R9X6
U2 = LQFP48_0R5_9X9
U3 = SOT-23-5L
U4 = DFN6_0R95_3X3
U5 = SON8_1R27_6X8
U6 = DFN8_1R27_6X8_TP4R6X5R3
U7 = BGA72_0R5_4R5X4
U8 = BGA176_0R65_10X10
U9 U11 = SOT-223
U10 = FBGA48_0R75_6X8
U12 = SON8_0R65_3X3
U13 U14 = SOT23-5
U15 = QFN8_0R5_2R5X1R2
U16-U19 = MP34DT01TR
U20 = QFN16_0R4_2R5X1R7
U21 U22 = SOT23-6
U23 = D0201_21
U24 = DO_2SM_1R6X1_21
X1 = XTAL_2SM_3R2X2R5_H1
X2 = XTAL_2SM_3R2X1R5
X3 = OSC_4SM_2R5X2
Z1 = DO-216AA

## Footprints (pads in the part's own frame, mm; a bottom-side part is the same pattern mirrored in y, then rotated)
0402C
  rect 0.559x0.559 smd: 1(-0.508,0) 2(0.508,0)
0402R
  rect 0.559x0.559 smd: 1(-0.508,0) 2(0.508,0)
0603C
  rect 0.889x0.813 smd: 1(-0.762,0) 2(0.762,0)
0603D
  rect 0.889x0.813 smd: 1(-0.762,0) 2(0.762,0)
0603L
  rect 0.889x0.813 smd: 1(-0.762,0) 2(0.762,0)
0603R
  rect 0.787x0.813 smd: 1(-0.762,0) 2(0.762,0)
0603R-GS
  rect 1.245x1.194 smd: 1(-0.775,0) 2(0.775,0)
0805C
  rect 1.143x1.27 smd: 1(-0.889,0) 2(0.889,0)
0805R
  rect 1.016x1.27 smd: 1(-0.889,0) 2(0.889,0)
1206C
  rect 1.168x1.524 smd: 1(-1.473,0) 2(1.473,0)
1210L
  rect 1.168x2.54 smd: 1(-1.473,0) 2(1.473,0)
BGA72_0R5_4R5X4
  round 0.249 smd: A1(-2,1.75) A2(-1.5,1.75) A3(-1,1.75) A4(-0.5,1.75) A5(0,1.75) A6(0.5,1.75) A7(1,1.75) A8(1.5,1.75) A9(2,1.75) B1(-2,1.25) B2(-1.5,1.25) B3(-1,1.25) B4(-0.5,1.25) B5(0,1.25) B6(0.5,1.25) B7(1,1.25) B8(1.5,1.25) B9(2,1.25) C1(-2,0.75) C2(-1.5,0.75) C3(-1,0.75) C4(-0.5,0.75) C5(0,0.75) C6(0.5,0.75) C7(1,0.75) C8(1.5,0.75) C9(2,0.75) D1(-2,0.25) D2(-1.5,0.25) D3(-1,0.25) D4(-0.5,0.25) D5(0,0.25) D6(0.5,0.25) D7(1,0.25) D8(1.5,0.25) D9(2,0.25) E1(-2,-0.25) E2(-1.5,-0.25) E3(-1,-0.25) E4(-0.5,-0.25) E5(0,-0.25) E6(0.5,-0.25) E7(1,-0.25) E8(1.5,-0.25) E9(2,-0.25) F1(-2,-0.75) F2(-1.5,-0.75) F3(-1,-0.75) F4(-0.5,-0.75) F5(0,-0.75) F6(0.5,-0.75) F7(1,-0.75) F8(1.5,-0.75) F9(2,-0.75) G1(-2,-1.25) G2(-1.5,-1.25) G3(-1,-1.25) G4(-0.5,-1.25) G5(0,-1.25) G6(0.5,-1.25) G7(1,-1.25) G8(1.5,-1.25) G9(2,-1.25) H1(-2,-1.75) H2(-1.5,-1.75) H3(-1,-1.75) H4(-0.5,-1.75) H5(0,-1.75) H6(0.5,-1.75) H7(1,-1.75) H8(1.5,-1.75) H9(2,-1.75)
BGA176_0R65_10X10
  round 0.305 smd: A1(-4.55,4.55) A2(-3.9,4.55) A3(-3.25,4.55) A4(-2.6,4.55) A5(-1.95,4.55) A6(-1.3,4.55) A7(-0.65,4.55) A8(0,4.55) A9(0.65,4.55) A10(1.3,4.55) A11(1.95,4.55) A12(2.6,4.55) A13(3.25,4.55) A14(3.9,4.55) A15(4.55,4.55) B1(-4.55,3.9) B2(-3.9,3.9) B3(-3.25,3.9) B4(-2.6,3.9) B5(-1.95,3.9) B6(-1.3,3.9) B7(-0.65,3.9) B8(0,3.9) B9(0.65,3.9) B10(1.3,3.9) B11(1.95,3.9) B12(2.6,3.9) B13(3.25,3.9) B14(3.9,3.9) B15(4.55,3.9) C1(-4.55,3.25) C2(-3.9,3.25) C3(-3.25,3.25) C4(-2.6,3.25) C5(-1.95,3.25) C6(-1.3,3.25) C7(-0.65,3.25) C8(0,3.25) C9(0.65,3.25) C10(1.3,3.25) C11(1.95,3.25) C12(2.6,3.25) C13(3.25,3.25) C14(3.9,3.25) C15(4.55,3.25) D1(-4.55,2.6) D2(-3.9,2.6) D3(-3.25,2.6) D4(-2.6,2.6) D5(-1.95,2.6) D6(-1.3,2.6) D7(-0.65,2.6) D8(0,2.6) D9(0.65,2.6) D10(1.3,2.6) D11(1.95,2.6) D12(2.6,2.6) D13(3.25,2.6) D14(3.9,2.6) D15(4.55,2.6) E1(-4.55,1.95) E2(-3.9,1.95) E3(-3.25,1.95) E4(-2.6,1.95) E12(2.6,1.95) E13(3.25,1.95) E14(3.9,1.95) E15(4.55,1.95) F1(-4.55,1.3) F2(-3.9,1.3) F3(-3.25,1.3) F4(-2.6,1.3) F6(-1.3,1.3) F7(-0.65,1.3) F8(0,1.3) F9(0.65,1.3) F10(1.3,1.3) F12(2.6,1.3) F13(3.25,1.3) F14(3.9,1.3) F15(4.55,1.3) G1(-4.55,0.65) G2(-3.9,0.65) G3(-3.25,0.65) G4(-2.6,0.65) G6(-1.3,0.65) G7(-0.65,0.65) G8(0,0.65) G9(0.65,0.65) G10(1.3,0.65) G12(2.6,0.65) G13(3.25,0.65) G14(3.9,0.65) G15(4.55,0.65) H1(-4.55,0) H2(-3.9,0) H3(-3.25,0) H4(-2.6,0) H6(-1.3,0) H7(-0.65,0) H8(0,0) H9(0.65,0) H10(1.3,0) H12(2.6,0) H13(3.25,0) H14(3.9,0) H15(4.55,0) J1(-4.55,-0.65) J2(-3.9,-0.65) J3(-3.25,-0.65) J4(-2.6,-0.65) J6(-1.3,-0.65) J7(-0.65,-0.65) J8(0,-0.65) J9(0.65,-0.65) J10(1.3,-0.65) J12(2.6,-0.65) J13(3.25,-0.65) J14(3.9,-0.65) J15(4.55,-0.65) K1(-4.55,-1.3) K2(-3.9,-1.3) K3(-3.25,-1.3) K4(-2.6,-1.3) K6(-1.3,-1.3) K7(-0.65,-1.3) K8(0,-1.3) K9(0.65,-1.3) K10(1.3,-1.3) K12(2.6,-1.3) K13(3.25,-1.3) K14(3.9,-1.3) K15(4.55,-1.3) L1(-4.55,-1.95) L2(-3.9,-1.95) L3(-3.25,-1.95) L4(-2.6,-1.95) L12(2.6,-1.95) L13(3.25,-1.95) L14(3.9,-1.95) L15(4.55,-1.95) M1(-4.55,-2.6) M2(-3.9,-2.6) M3(-3.25,-2.6) M4(-2.6,-2.6) M5(-1.95,-2.6) M6(-1.3,-2.6) M7(-0.65,-2.6) M8(0,-2.6) M9(0.65,-2.6) M10(1.3,-2.6) M11(1.95,-2.6) M12(2.6,-2.6) M13(3.25,-2.6) M14(3.9,-2.6) M15(4.55,-2.6) N1(-4.55,-3.25) N2(-3.9,-3.25) N3(-3.25,-3.25) N4(-2.6,-3.25) N5(-1.95,-3.25) N6(-1.3,-3.25) N7(-0.65,-3.25) N8(0,-3.25) N9(0.65,-3.25) N10(1.3,-3.25) N11(1.95,-3.25) N12(2.6,-3.25) N13(3.25,-3.25) N14(3.9,-3.25) N15(4.55,-3.25) P1(-4.55,-3.9) P2(-3.9,-3.9) P3(-3.25,-3.9) P4(-2.6,-3.9) P5(-1.95,-3.9) P6(-1.3,-3.9) P7(-0.65,-3.9) P8(0,-3.9) P9(0.65,-3.9) P10(1.3,-3.9) P11(1.95,-3.9) P12(2.6,-3.9) P13(3.25,-3.9) P14(3.9,-3.9) P15(4.55,-3.9) R1(-4.55,-4.55) R2(-3.9,-4.55) R3(-3.25,-4.55) R4(-2.6,-4.55) R5(-1.95,-4.55) R6(-1.3,-4.55) R7(-0.65,-4.55) R8(0,-4.55) R9(0.65,-4.55) R10(1.3,-4.55) R11(1.95,-4.55) R12(2.6,-4.55) R13(3.25,-4.55) R14(3.9,-4.55) R15(4.55,-4.55)
D0201_21
  rect 0.305x0.305 smd: 1(-0.28,0) 2(0.28,0)
DF37NB-10DS-0R4V
  rect 0.203x0.686 smd: 1(0.8,-1.325) 2(0.4,-1.325) 3(0,-1.325) 4(-0.4,-1.325) 5(-0.8,-1.325) 6(-0.8,1.325) 7(-0.4,1.325) 8(0,1.325) 9(0.4,1.325) 10(0.8,1.325)
  rect 0.406x1.092 smd: 11(-2.04,0) 12(2.04,0)
DFN6_0R95_3X3
  rect 0.457x0.711 smd: 1(-0.95,-1.436) 2(0,-1.436) 3(0.95,-1.436) 4(0.95,1.436) 5(0,1.436) 6(-0.95,1.436)
  rect 2.413x1.651 smd: 7(0,0)
DFN8_1R27_6X8_TP4R6X5R3
  rect 0.559x0.914 smd: 1(-1.905,-3.9) 2(-0.635,-3.9) 3(0.635,-3.9) 4(1.905,-3.9) 5(1.905,3.9) 6(0.635,3.9) 7(-0.635,3.9) 8(-1.905,3.9)
  rect 4.572x5.334 smd: 9(0,0)
DO-216AA
  rect 1.143x0.813 smd: 1(0,0)
  rect 2.286x2.261 smd: 2(-2.286,0)
DO_2SM_1R6X1_21
  rect 0.559x0.787 smd: 1(-0.625,0) 2(0.625,0)
FBGA48_0R75_6X8
  round 0.356 smd: A1(-1.875,2.625) A2(-1.125,2.625) A3(-0.375,2.625) A4(0.375,2.625) A5(1.125,2.625) A6(1.875,2.625) B1(-1.875,1.875) B2(-1.125,1.875) B3(-0.375,1.875) B4(0.375,1.875) B5(1.125,1.875) B6(1.875,1.875) C1(-1.875,1.125) C2(-1.125,1.125) C3(-0.375,1.125) C4(0.375,1.125) C5(1.125,1.125) C6(1.875,1.125) D1(-1.875,0.375) D2(-1.125,0.375) D3(-0.375,0.375) D4(0.375,0.375) D5(1.125,0.375) D6(1.875,0.375) E1(-1.875,-0.375) E2(-1.125,-0.375) E3(-0.375,-0.375) E4(0.375,-0.375) E5(1.125,-0.375) E6(1.875,-0.375) F1(-1.875,-1.125) F2(-1.125,-1.125) F3(-0.375,-1.125) F4(0.375,-1.125) F5(1.125,-1.125) F6(1.875,-1.125) G1(-1.875,-1.875) G2(-1.125,-1.875) G3(-0.375,-1.875) G4(0.375,-1.875) G5(1.125,-1.875) G6(1.875,-1.875) H1(-1.875,-2.625) H2(-1.125,-2.625) H3(-0.375,-2.625) H4(0.375,-2.625) H5(1.125,-2.625) H6(1.875,-2.625)
FH26-29S-0R3SHW
  rect 0.406x0.94 smd: (-4.9,-1.2) (4.9,-1.2)
  rect 0.305x0.813 smd: 1(-4.2,-1.45) 3(-3.6,-1.45) 5(-3,-1.45) 7(-2.4,-1.45) 9(-1.8,-1.45) 11(-1.2,-1.45) 13(-0.6,-1.45) 15(0,-1.45) 17(0.6,-1.45) 19(1.2,-1.45) 21(1.8,-1.45) 23(2.4,-1.45) 25(3,-1.45) 27(3.6,-1.45) 29(4.2,-1.45)
  rect 0.279x0.813 smd: 2(-3.9,1.45) 4(-3.3,1.45) 6(-2.7,1.45) 8(-2.1,1.45) 10(-1.5,1.45) 12(-0.9,1.45) 14(-0.3,1.45) 16(0.3,1.45) 18(0.9,1.45) 20(1.5,1.45) 22(2.1,1.45) 24(2.7,1.45) 26(3.3,1.45) 28(3.9,1.45)
HDR_1X2_2R54_RA_11R35
  rect 1.524x1.524 hole 1.016: 1(0,0)
  round 1.524 hole 1.016: 2(-2.54,0)
HDR_1X4_2R54
  rect 1.321x1.321 hole 0.914: 1(0,0)
  round 1.321 hole 0.914: 2(2.54,0) 3(5.08,0) 4(7.62,0)
HDR_1X6_2R54_W
  rect 1.524x1.524 hole 1.016: 1(0,0)
  round 1.524 hole 1.016: 2(2.54,0) 3(5.08,0) 4(7.62,0) 5(10.16,0) 6(12.7,0)
HDR_1X8_2R54_W
  rect 1.524x1.524 hole 1.016: 1(0,0)
  round 1.524 hole 1.016: 2(2.54,0) 3(5.08,0) 4(7.62,0) 5(10.16,0) 6(12.7,0) 7(15.24,0) 8(17.78,0)
HDR_1X10_2R54_W
  rect 1.524x1.524 hole 1.016: 1(0,0)
  round 1.524 hole 1.016: 2(2.54,0) 3(5.08,0) 4(7.62,0) 5(10.16,0) 6(12.7,0) 7(15.24,0) 8(17.78,0) 9(20.32,0) 10(22.86,0)
HDR_2X4_2R54
  rect 1.321x1.321 hole 0.914: 1(0,0)
  round 1.321 hole 0.914: 2(0,2.54) 3(2.54,0) 4(2.54,2.54) 5(5.08,0) 6(5.08,2.54) 7(7.62,0) 8(7.62,2.54)
HOLE_C6D3R5
  round 5.994 hole 3.505: 1(0,0)
JP2_SMD
  round 0.152 smd: 1(-0.584,-0.008) 2(0.402,-0.03)
LED2_3528
  rect 1.118x1.499 smd: 1(-0.75,-1.5) 2(-0.75,1.5) 3(0.75,1.5) 4(0.75,-1.5)
LQFP48_0R5_9X9
  rect 1.346x0.279 smd: 1(-4.35,2.75) 2(-4.35,2.25) 3(-4.35,1.75) 4(-4.35,1.25) 5(-4.35,0.75) 6(-4.35,0.25) 7(-4.35,-0.25) 8(-4.35,-0.75) 9(-4.35,-1.25) 10(-4.35,-1.75) 11(-4.35,-2.25) 12(-4.35,-2.75) 25(4.35,-2.75) 26(4.35,-2.25) 27(4.35,-1.75) 28(4.35,-1.25) 29(4.35,-0.75) 30(4.35,-0.25) 31(4.35,0.25) 32(4.35,0.75) 33(4.35,1.25) 34(4.35,1.75) 35(4.35,2.25) 36(4.35,2.75)
  rect 0.279x1.346 smd: 13(-2.75,-4.35) 14(-2.25,-4.35) 15(-1.75,-4.35) 16(-1.25,-4.35) 17(-0.75,-4.35) 18(-0.25,-4.35) 19(0.25,-4.35) 20(0.75,-4.35) 21(1.25,-4.35) 22(1.75,-4.35) 23(2.25,-4.35) 24(2.75,-4.35) 37(2.75,4.35) 38(2.25,4.35) 39(1.75,4.35) 40(1.25,4.35) 41(0.75,4.35) 42(0.25,4.35) 43(-0.25,4.35) 44(-0.75,4.35) 45(-1.25,4.35) 46(-1.75,4.35) 47(-2.25,4.35) 48(-2.75,4.35)
MICRO_USB_B_105017
  rect 0.406x1.346 smd: 1(-1.3,0.075) 2(-0.65,0.075) 3(0,0.075) 4(0.65,0.075) 5(1.3,0.075)
  oval 1.194x1.905 hole 0.61x1.295: 6(-3.5,-2.6) 7(3.5,-2.6)
  round 1.499 hole 0.838: 8(-2.5,0.1) 9(2.5,0.1)
  rect 1.499x1.905 smd: 10(-1,-2.6) 11(1,-2.6)
MOLEX_47590001
  rect 0.406x1.346 smd: 1(1.3,0) 2(0.65,0) 3(0,0) 4(-0.65,0) 5(-1.3,0)
  oval 1.067x1.6 hole 0.762x0.838: 6(2.275,0.325) 7(-2.275,0.325)
  oval 1.397x1.905 hole 0.838x1.499: 8(-4.15,-2.855) 9(4.15,-2.855)
  rect 2.896x2.007 smd: 10(0,-2.675)
MP34DT01TR
  rect 0.508x1.067 smd: 1(-0.425,0.675) 2(-0.425,-0.675) 3(0.425,-0.675) 4(0.425,0.675)
  round 0.152 smd: 5(-0.025,-1.753)
OSC_4SM_2R5X2
  rect 1.041x0.94 smd: 1(-0.925,-0.725) 2(0.925,-0.725) 3(0.925,0.725) 4(-0.925,0.725)
PJ3028B
  round 2.007 hole 2.007 unplated: (0,0) (7,0)
  rect 1.219x2.489 smd: 2(-3.9,-4) 7(-2,4)
  rect 2.007x2.489 smd: 3(-1,-4) 4(0.8,4) 6(8.2,-4)
  rect 2.489x2.007 smd: 5(12.25,0.8)
QFN8_0R5_2R5X1R2
  custom 0.1x0.1 smd: 1(-0.75,-0.5) 4(0.75,-0.5) 5(0.75,0.5) 8(-0.75,0.5)
  rect 0.203x0.61 smd: 2(-0.25,-0.5) 3(0.25,-0.5) 6(0.25,0.5) 7(-0.25,0.5)
QFN16_0R4_2R5X1R7
  oval 0.203x0.61 smd: 1(-0.6,-0.905) 2(-0.2,-0.905) 3(0.2,-0.905) 4(0.6,-0.905) 9(0.6,0.905) 10(0.2,0.905) 11(-0.2,0.905) 12(-0.6,0.905)
  oval 0.61x0.203 smd: 5(1.305,-0.6) 6(1.305,-0.2) 7(1.305,0.2) 8(1.305,0.6) 13(-1.305,0.6) 14(-1.305,0.2) 15(-1.305,-0.2) 16(-1.305,-0.6)
  rect 1.499x0.711 smd: 17(0,0)
R0603
  rect 0.787x0.813 smd: 1(-0.762,0) 2(0.762,0)
SIP2
  rect 1.524x1.524 hole 1.016: 1(0,0)
  round 1.524 hole 1.016: 2(2.54,0)
SOD-323
  rect 0.813x0.813 smd: 1(1.125,0) 2(-1.125,0)
SOIC8_1R27_4R9X6
  rect 0.559x1.778 smd: 1(-1.905,-2.624) 2(-0.635,-2.624) 3(0.635,-2.624) 4(1.905,-2.624) 5(1.905,2.624) 6(0.635,2.624) 7(-0.635,2.624) 8(-1.905,2.624)
SON8_0R65_3X3
  rect 0.406x0.787 smd: 1(-0.975,-1.475) 2(-0.325,-1.475) 3(0.325,-1.475) 4(0.975,-1.475) 5(0.975,1.475) 6(0.325,1.475) 7(-0.325,1.475) 8(-0.975,1.475)
  custom 0.4x0.4 smd: 9(0,0)
SON8_1R27_6X8
  rect 0.559x0.914 smd: 1(-1.905,-3.9) 2(-0.635,-3.9) 3(0.635,-3.9) 4(1.905,-3.9) 5(1.905,3.9) 6(0.635,3.9) 7(-0.635,3.9) 8(-1.905,3.9)
  rect 4.597x4.699 smd: 9(0,0)
SOT23-5
  rect 0.635x1.143 smd: 1(-0.95,-1.2) 2(0,-1.2) 3(0.95,-1.2) 4(0.95,1.2) 5(-0.95,1.2)
SOT23-6
  rect 0.635x1.346 smd: 1(-0.95,-1.2) 2(0,-1.2) 3(0.95,-1.2) 4(0.95,1.2) 5(0,1.2) 6(-0.95,1.2)
SOT-23
  rect 1.143x0.635 smd: 1(1.1,-0.95) 2(1.1,0.95) 3(-1.1,0)
SOT-23-5L
  rect 0.635x1.143 smd: 1(-0.95,-1.2) 2(0,-1.2) 3(0.95,-1.2) 4(0.95,1.2) 5(-0.95,1.2)
SOT-223
  rect 1.803x1.016 smd: 1(3.15,-2.3) 2(3.15,0) 3(3.15,2.3)
  rect 1.803x3.302 smd: 4(-3.15,0)
SQT-110-01-F-D-RA
  rect 1.321x1.321 hole 0.914: 1(9,1)
  round 1.321 hole 0.914: 2(7,1) 3(5,1) 4(3,1) 5(1,1) 6(-1,1) 7(-3,1) 8(-5,1) 9(-7,1) 10(-9,1) 11(9,-1) 12(7,-1) 13(5,-1) 14(3,-1) 15(1,-1) 16(-1,-1) 17(-3,-1) 18(-5,-1) 19(-7,-1) 20(-9,-1)
SSW-106-02-F-D-RA
  rect 1.524x1.524 hole 1.016: 1(0,0)
  round 1.524 hole 1.016: 2(-2.54,0) 3(-5.08,0) 4(-7.62,0) 5(-10.16,0) 6(-12.7,0) 7(0,-2.54) 8(-2.54,-2.54) 9(-5.08,-2.54) 10(-7.62,-2.54) 11(-10.16,-2.54) 12(-12.7,-2.54)
TACT_4SM_3R5X5R5
  rect 1.016x1.27 smd: 1(0.85,-2.425) 2(-0.85,-2.425) 3(0.85,2.425) 4(-0.85,2.425)
TAN-A
  rect 1.27x1.524 smd: 1(1.397,0) 2(-1.397,0)
TC2050-IDC-NL
  round 0.991 hole 0.991 unplated: (-3.81,0) (3.81,1.015) (3.81,-1.015)
  round 0.787 smd: 1(-2.54,-0.635) 2(-1.27,-0.635) 3(0,-0.635) 4(1.27,-0.635) 5(2.54,-0.635) 6(2.54,0.635) 7(1.27,0.635) 8(0,0.635) 9(-1.27,0.635) 10(-2.54,0.635)
TP_C40
  round 1.016 smd: 1(0,0)
TSM-105-01-S-DV
  rect 1.27x3.683 smd: 1(-5.08,-2.475) 2(-5.08,2.475) 3(-2.54,-2.475) 4(-2.54,2.475) 5(0,-2.475) 6(0,2.475) 7(2.54,-2.475) 8(2.54,2.475) 9(5.08,-2.475) 10(5.08,2.475)
unnamed#2
  round 1.016 smd: (0,0)
XTAL_2SM_3R2X1R5
  rect 1.295x1.6 smd: 1(-1.15,0) 2(1.15,0)
XTAL_2SM_3R2X2R5_H1
  rect 1.803x2.692 smd: 1(-1.15,0) 2(1.15,0)

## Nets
1V8: C20.1 C23.1 C42.1 C57.2 U7.D1 U7.D8 U7.G9 U9.2 U9.4
3V3: B1.1 B1.3 C2.1 C13.2 C15.2 C16.2 C22.1 C33.1 C35.2 C41.1 C55.2 C63.2 C71.2 C92.1 CN12.2 CN12.4 CN14.2 CN16.9 CN17.26 JP1.2 L2.1 P2.6 P2.12 R27.2 R30.2 R41.1 R42.1 R43.1 R44.1 R45.1 R46.2 R52.1 R55.1 R56.2 R57.2 R59.2 R60.2 R63.2 R71.1 R73.2 R79.2 R80.1 R81.1 R82.2 R83.2 R84.2 R91.2 R93.1 R94.1 R95.1 R96.1 R100.2 R102.2 SB1.1 SB4.2 U4.4 U5.8 U6.8 U7.B2 U7.C2 U7.D2 U7.E9 U9.3 U10.D6 U10.E1 U20.2 X3.4
3V3_ST_LINK: C1.1 C11.2 C12.2 C81.2 C82.2 C83.2 CN2.1 CN9.1 LD4.4 R5.2 R24.2 R25.1 T3.3 U2.1 U2.9 U2.24 U2.36 U2.48 U3.5
5V: C14.2 C17.2 CN8.2 CN8.4 CN8.6 CN8.8 CN8.10 CN12.5 D1.1 L3.1 P1.6 P1.15 R1.1 U4.1 U4.6 U13.5 U14.5
5V_ST_LINK: C5.2 CN8.1 SB3.2 U1.6 U1.7
5V_USB_FS: CN8.7 D3.1 R99.2
5V_USB_HS: C78.1 CN8.3 CN19.1 D5.1 R74.2 R98.2 U13.1 U15.1
5V_USB_ST_LINK: C3.2 CN1.1 CN8.9 D2.1 R2.2 R11.1 R15.2 R20.2 SB3.1 U1.1 U1.2 U21.5
GND: B2.2 B2.4 C1.2 C2.2 C3.1 C4.1 C5.1 C6.1 C7.1 C8.1 C9.1 C10.1 C11.1 C12.1 C13.1 C14.1 C15.1 C16.1 C17.1 C19.1 C20.2 C21.2 C22.2 C23.2 C24.2 C26.2 C28.2 C29.1 C31.1 C33.2 C34.2 C35.1 C36.1 C37.1 C38.1 C39.1 C40.1 C41.2 C42.2 C43.1 C44.1 C45.1 C46.1 C47.1 C48.1 C49.1 C50.1 C51.1 C52.1 C53.1 C54.2 C55.1 C56.1 C57.1 C58.1 C59.1 C60.1 C61.1 C62.1 C63.1 C64.2 C65.2 C66.2 C68.1 C71.1 C74.1 C77.2 C78.2 C79.2 C80.2 C81.1 C82.1 C83.1 C84.2 C85.2 C86.1 C87.1 C92.2 C93.1 CN1.5 CN1.6 CN1.7 CN1.8 CN1.9 CN1.10 CN1.11 CN2.3 CN3.2 CN4.3 CN5.3 CN9.3 CN9.5 CN11.7 CN12.6 CN12.7 CN14.7 CN16.1 CN16.3 CN16.6 CN16.10 CN17.1 CN17.27 CN18.5 CN18.6 CN18.7 CN18.8 CN18.9 CN18.10 CN19.5 CN19.6 CN19.7 CN19.8 CN19.9 CN19.10 H1.1 H2.1 H4.1 L5.1 LD1.2 LD2.2 LD4.1 LD5.2 LD6.2 P1.5 P1.16 P2.5 P2.11 R3.1 R6.1 R8.1 R9.1 R16.1 R17.1 R18.1 R19.1 R21.1 R22.2 R26.1 R29.1 R31.2 R33.2 R36.1 R37.1 R54.2 R61.1 R75.2 R76.1 R89.1 SB2.2 SB6.1 SB16.1 T1.2 T2.2 U1.4 U2.8 U2.20 U2.23 U2.35 U2.47 U3.2 U4.2 U4.7 U5.4 U6.4 U7.A1 U7.A3 U7.A4 U7.A5 U7.C1 U7.D6 U7.E2 U7.E7 U7.E8 U7.F7 U7.G5 U7.H9 U8.D5 U8.D7 U8.D8 U8.D9 U8.F2 U8.F6 U8.F7 U8.F8 U8.F9 U8.F10 U8.F12 U8.G2 U8.G6 U8.G7 U8.G8 U8.G9 U8.G10 U8.G12 U8.H6 U8.H7 U8.H8 U8.H9 U8.H10 U8.H12 U8.J6 U8.J7 U8.J8 U8.J9 U8.J10 U8.K6 U8.K7 U8.K8 U8.K9 U8.K10 U8.M1 U8.M8 U8.M9 U8.N1 U9.1 U10.D1 U10.E6 U10.H1 U11.1 U13.2 U14.2 U15.5 U15.8 U16.5 U17.5 U18.2 U18.5 U19.2 U19.5 U20.11 U21.2 U22.2 U23.2 U24.2 X3.2
V12_OTGPHY: C54.1 U8.J14
VDD: C34.1 C36.2 C37.2 C38.2 C39.2 C40.2 C44.2 C45.2 C46.2 C47.2 C52.2 C53.2 C56.2 C61.2 C62.2 C66.1 CN17.25 JP1.1 L1.1 R27.1 R68.1 R70.1 SB15.1 U8.C1 U8.C5 U8.C7 U8.C8 U8.C9 U8.F3 U8.G3 U8.G13 U8.H13 U8.J12 U8.J13 U8.K4 U8.N8 U8.N9 U8.N10
VDDA: C60.2 C65.1 L1.2 R62.2 U8.R1
VIN: C74.2 CN12.8 U11.3
AIN_1: R25.2 R26.2 U2.10
ARD_A0: CN15.1 U8.P3
ARD_A1: CN15.2 SB28.2 U8.N4
ARD_A2: CN15.3 U8.N5
ARD_A3: CN15.4 U8.L1
ARD_A4: SB35.1 U8.M2
ARD_A5: SB37.1 U8.M3
ARD_D0: CN13.1 U8.R2
ARD_D1: CN13.2 U8.P2
ARD_D2: CN13.3 U8.P5
ARD_D3: CN13.4 U8.B2
ARD_D4: CN13.5 U8.G4
ARD_D5: CN13.6 SB29.2 U8.R5
ARD_D6: CN13.7 U8.B3
ARD_D7: CN13.8 U8.A1
ARD_D8: CN11.1 U8.B1
ARD_D9: CN11.2 U8.M11
ARD_D10: CN11.3 U8.N2
ARD_D11: CN11.4 U8.A6
ARD_D12: CN11.5 U8.A9
ARD_D13: CN11.6 SB14.2 U8.P4
ARD_D14: CN11.9 R59.1 SB27.1 SB36.1 U8.J4
ARD_D15: CN11.10 R60.1 SB25.1 SB38.1 U8.H4
BLGND: C67.2 C69.1 C70.1 C72.1 C73.1 C75.1 C76.1 L5.2 R66.1 R67.1 R69.1 U12.3 U12.9
BOOT0: R36.2 R43.2 U8.D6
BYPASSREG: R61.2 U8.L4
CTP_INT: CN16.2 R21.2 U8.D3
CTP_RST: CN16.7 R18.2 U8.M13
CTP_SCL: CN16.5 R52.2 U8.F15
CTP_SDA: CN16.4 R56.1 U8.M12
DMIC_VDD: C79.1 C80.1 C84.1 C85.1 R85.2 R86.2 SB1.2 SB5.2 U16.1 U17.1 U18.1 U19.1
DMICCLK: U7.C6 U16.3 U17.3 U18.3 U19.3
DMICDAT1: U7.B9 U17.4 U18.4
DMICDAT2: U7.A9 U16.4 U19.4
E5V: C68.2 CN3.1 CN8.5 D4.1 R58.2 U11.2 U11.4
LCD-RS_A0: CN17.21 R101.2
LCD_BL: L7.1 U8.L12
LCD_NE: CN17.22 R70.2 U8.C10
LCD_PSRAM_D0: CN17.18 U8.M14 U10.B6
LCD_PSRAM_D1: CN17.17 U8.L14 U10.C5
LCD_PSRAM_D2: CN17.16 U8.B12 U10.C6
LCD_PSRAM_D3: CN17.15 U8.C12 U10.D5
LCD_PSRAM_D4: CN17.14 U8.R8 U10.E5
LCD_PSRAM_D5: CN17.13 U8.P8 U10.F5
LCD_PSRAM_D6: CN17.12 U8.P9 U10.F6
LCD_PSRAM_D7: CN17.11 U8.R9 U10.G6
LCD_PSRAM_D8: CN17.10 U8.P10 U10.B1
LCD_PSRAM_D9: CN17.9 U8.R10 U10.C1
LCD_PSRAM_D10: CN17.8 U8.N11 U10.C2
LCD_PSRAM_D11: CN17.7 U8.P11 U10.D2
LCD_PSRAM_D12: CN17.6 U8.R11 U10.E2
LCD_PSRAM_D13: CN17.5 U8.P15 U10.F2
LCD_PSRAM_D14: CN17.4 U8.P14 U10.F1
LCD_PSRAM_D15: CN17.3 U8.N15 U10.G1
LCD_PSRAM_NOE: CN17.19 U8.D10 U10.A2
LCD_PSRAM_NWE: CN17.20 R64.1 U8.C11
LCD_RST: CN17.23 R68.2 U8.N12
LCD_TE_INT: CN17.2 U8.G14
LED_STLINK: R13.1 R14.1 U2.30
LEDA: CN17.28 L8.2
LEDK: CN17.29 R66.2 U12.4
MIC_VDD1: C29.2 SB5.1 TP1.1 U7.A7
MIC_VDD2: C31.2 TP2.1 U7.B6
NC1: TP3.1 U8.B5
NC4: TP5.1 U8.B9
NC8: TP14.1 U8.D2
NC10: TP8.1 U8.E4
NC11: TP13.1 U8.D1
NETB1_2: B1.2 B1.4 R89.2 R90.2
NETB2_1: B2.1 B2.3 C87.2 R91.1 SB34.2
NETC8_2: C8.2 U3.4
NETC9_2: C9.2 C10.2 SB7.2 U3.1 U3.3
NETC18_1: C18.1 U7.B7
NETC18_2: C18.2 CN4.4
NETC19_2: C19.2 U7.C9
NETC21_1: C21.1 U7.D9
NETC24_1: C24.1 U7.E6
NETC25_1: C25.1 U7.H8
NETC25_2: C25.2 U7.G8
NETC26_1: C26.1 U7.G7
NETC27_1: C27.1 U7.D7
NETC27_2: C27.2 CN4.6
NETC28_1: C28.1 U7.H7
NETC30_1: C30.1 CN5.6 U7.H6
NETC30_2: C30.2 R31.1
NETC32_1: C32.1 CN5.4 U7.G6
NETC32_2: C32.2 R33.1
NETC43_2: C43.2 U7.F1
NETC48_2: C48.2 R49.1 X2.1
NETC51_2: C51.2 R50.1 X2.2
NETC67_1: C67.1 C69.2 L2.2 L3.2 L4.1
NETC75_2: C75.2 C76.2 L8.1 U12.6 Z1.2
NETC86_2: C86.2 R90.1 SB33.2
NETCN7_1: CN7.1 U7.C3
NETCN7_2: CN7.2 U7.B3
NETCN10_1: CN10.1 U7.B1
NETCN10_2: CN10.2 U7.A2
NETCN11_8: CN11.8 R53.1
NETCN12_1: CN12.1 R58.1
NETCN14_1: CN14.1 R92.2
NETCN14_8: CN14.8 R97.1
NETCN15_5: CN15.5 SB35.2 SB36.2
NETCN15_6: CN15.6 SB37.2 SB38.2
NETCN16_8: CN16.8 SB2.1 SB4.1
NETCN17_24: CN17.24 SB15.2 SB16.2
NETD1_2: D1.2 R4.2
NETD2_2: D2.2 D3.2 D4.2 D5.2 SB7.1
NETL6_2: L6.2 U12.8 Z1.1
NETL7_2: L7.2 R69.2 R71.2 U12.7
NETLD1_1: LD1.1 R12.1
NETLD2_1: LD2.1 R1.2
NETLD3_1: LD3.1 R2.1
NETLD3_2: LD3.2 R15.1 U1.8
NETLD4_2: LD4.2 R14.2
NETLD4_3: LD4.3 R13.2
NETLD5_1: LD5.1 R47.2
NETLD6_1: LD6.1 R48.2
NETLD7_1: LD7.1 R81.2
NETLD7_2: LD7.2 R78.1 R80.2 U13.3
NETLD8_1: LD8.1 R82.1
NETLD8_2: LD8.2 T1.3
NETLD9_1: LD9.1 R83.1
NETLD9_2: LD9.2 T2.3
NETLD10_1: LD10.1 R84.1
NETR3_2: R3.2 U2.44
NETR7_1: R7.1 R8.2 R11.2 T3.1
NETR10_1: R10.1 T3.2
NETR12_2: R12.2 SB14.1
NETR17_2: R17.2 U2.2
NETR19_2: R19.2 U2.3
NETR22_1: R22.1 U1.5
NETR35_2: R35.2 U7.F3
NETR39_2: R39.2 U7.H1
NETR41_2: R41.2 U7.G2
NETR46_1: R46.1 U7.D4 U7.D5
NETR55_2: R55.2 X3.1
NETR63_1: R63.1 R65.2 U10.B5
NETR64_2: R64.2 U10.G5
NETR67_2: R67.2 U12.2
NETR72_2: R72.2 R73.1 U14.4
NETR74_1: R74.1 R75.1 T1.1
NETR76_2: R76.2 R77.1 T2.1
NETR85_1: R85.1 U16.2
NETR86_1: R86.1 U17.2
NETR100_1: R100.1 U10.A6
NRST: C93.2 CN12.3 R28.2 R57.1 SB10.2 SB34.1 U8.J1
OSC_25M: R51.1 X3.3
OSC_IN: C4.2 U2.5 X1.2
OSC_OUT: C6.2 U2.6 X1.1
PC14-OSC32_IN: R49.2 U8.E1
PC15-OSC32_OUT: R50.2 U8.F1
PDRON: R37.2 R45.2 U8.C6
PH0-OSCIN: R51.2 U8.G1
PH1-OSCOUT: TP15.1 U8.H1
PMOD#1: P1.1 P2.1 U20.8
PMOD#2: P1.2 P2.2 U20.16
PMOD#3: P1.3 P2.3 U20.5
PMOD#4: P1.4 P2.4 U20.13
PMOD_GPIO_0: P2.9 U8.B8
PMOD_GPIO_1: P2.10 U8.F4
PMOD_INT: P1.11 P2.7 U8.R13
PMOD_RESET: P1.12 P2.8 U8.R6
PMOD_SEL_0: R102.1 U8.D13 U20.3
PMOD_SEL_1: R29.2 U8.E3 U20.10
PMOD_SPI2_MISO: U8.C14 U20.6
PMOD_SPI2_MOSI: U8.C13 U20.1
PMOD_SPI2_NSS: U8.E14 U20.9
PMOD_SPI2_SCK: U8.D14 U20.14
PMOD_UART7_CTS: U8.L2 U20.7
PMOD_UART7_RTS: U8.L3 U20.12
PMOD_UART7_RXD: U8.K2 U20.4
PMOD_UART7_TXD: U8.K1 U20.15
PSRAM_A0: R101.1 U8.E2 U10.A3
PSRAM_A1: U8.H3 U10.A4
PSRAM_A2: U8.H2 U10.A5
PSRAM_A3: U8.J2 U10.B3
PSRAM_A4: U8.J3 U10.B4
PSRAM_A5: U8.K3 U10.C3
PSRAM_A6: U8.P6 U10.C4
PSRAM_A7: U8.N6 U10.D4
PSRAM_A8: U8.R7 U10.H2
PSRAM_A9: U8.P7 U10.H3
PSRAM_A10: U8.N7 U10.H4
PSRAM_A11: U8.M7 U10.H5
PSRAM_A12: U8.L15 U10.G3
PSRAM_A13: U8.K15 U10.G4
PSRAM_A14: U8.K14 U10.F3
PSRAM_A15: U8.K13 U10.F4
PSRAM_A16: U8.N14 U10.E4
PSRAM_A17: U8.N13 U10.D3
PSRAM_NBL0: U8.A4 U10.A1
PSRAM_NBL1: U8.A3 U10.B2
PSRAM_NE1: R65.1 U8.A11
PWR_ENN: R20.1 U1.3 U2.28
PWR_EXT: R4.1 R5.1 R6.2 U2.39
QSPI_CLK: U5.6 U6.6 U8.M6
QSPI_D0: U5.5 U6.5 U8.F14
QSPI_D1: U5.2 U6.2 U8.B14
QSPI_D2: U5.3 U6.3 U8.A2
QSPI_D3: U5.7 U6.7 U8.M15
QSPI_NCS: R30.1 U5.1 U6.1 U8.B6
REXT_OTGPHY: R54.1 U8.J15
SAI2_FS_A: TP11.1 U7.E3 U8.C2
SAI2_I2C1_SCL: R39.1 R44.2 U8.A5
SAI2_I2C1_SDA: R35.1 R42.2 U8.B4
SAI2_INT: U7.G3 U8.B7
SAI2_MCLK_A: TP6.1 U7.D3 U8.D4
SAI2_SCK_A: TP7.1 U7.G1 U8.C4
SAI2_SD_A: TP12.1 U7.E4 U8.C3
SAI2_SD_B: TP4.1 U7.F2 U8.B10
STLINK_RX: SB9.2 U2.13
STLINK_TX: SB8.2 U2.12
STM_JTCK: CN2.2 U2.37
STM_JTMS: CN2.4 U2.34
STM_RST: C7.2 R24.1 SB6.2 U2.7
STMOD+_ADC_DAC: P1.13 SB28.1
STMOD+_I2C2_SCL: P1.7 SB25.2
STMOD+_I2C2_SDA: P1.10 SB27.2
STMOD+_SPI2_MISOS: P1.9 U8.M4
STMOD+_SPI2_MOSIS: P1.8 U8.M5
STMOD+_TIM2_CH1: P1.19 U8.A13
STMOD+_TIM3_CH3: P1.14 SB29.1
STMOD+_UART4_RXD: P1.18 U8.E13
STMOD+_UART4_RXD_S: P1.20 U8.B13
STMOD+_UART4_TXD: P1.17 U8.E12
SYS_B_USER: SB33.1 U8.N3
SYS_LD_USER1: R47.1 U8.R3
SYS_LD_USER2: R48.1 U8.R4
SYS_STLINK_JTCK: R38.2 SB12.2 U8.A14
SYS_STLINK_JTDO-SWO: R40.2 SB13.2 U8.A10
SYS_STLINK_JTMS: R32.2 SB11.2 U8.A15
T_JTCK: SB12.1 U2.15 U2.26
T_JTMS: R23.1 SB11.1 U2.27
T_NRST: SB10.1 U2.18
T_SWDIO_IN: R23.2 U2.25
T_SWO: SB13.1 U2.31
TAG_NRST: CN9.10 R28.1
TAG_SWCLK: CN9.4 R38.1
TAG_SWDIO: CN9.2 R32.1
TAG_SWO: CN9.6 R40.1
USB_OTGFS_CN_N: CN18.2 U22.6
USB_OTGFS_CN_P: CN18.3 U22.4
USB_OTGFS_ID: CN18.4 U8.D15 U23.1
USB_OTGFS_N: U8.C15 U22.1
USB_OTGFS_OVCR: LD10.2 R79.1 U8.R12 U14.3
USB_OTGFS_P: U8.B15 U22.3
USB_OTGFS_PPWR_EN: R72.1 U8.H14
USB_OTGFS_VBUS: C77.1 CN18.1 R77.2 R99.1 U8.E15 U14.1 U24.1
USB_OTGHS_CN_N: CN19.2 U15.2
USB_OTGHS_CN_P: CN19.3 U15.3
USB_OTGHS_ID: CN19.4 U8.P12 U15.4
USB_OTGHS_N: U8.R14 U15.7
USB_OTGHS_OVCR: R78.2 U8.L13
USB_OTGHS_P: U8.R15 U15.6
USB_OTGHS_PPWR_EN: R16.2 U8.K12 U13.4
USB_OTGHS_VBUS: R98.1 U8.P13
USB_RENUMN: R7.2 U2.38
USB_STLK_CN_N: CN1.2 U21.1
USB_STLK_CN_P: CN1.3 U21.3
USB_STLK_ID: CN1.4 R9.2
USB_STLK_N: U2.32 U21.6
USB_STLK_P: R10.2 U2.33 U21.4
VCAP1: C58.2 U8.M10
VCAP2: C49.2 U8.F13
VCP_RX: CN6.2 SB8.1 U8.G15
VCP_TX: CN6.1 SB9.1 U8.H15
VL: C70.2 C72.2 C73.2 L4.2 L6.1 U12.1
VREF+: C50.2 C59.2 C64.1 R53.2 R62.1 U8.P1
WIFI_CH_PD: CN14.6 R95.2 U8.D11
WIFI_GPIO_0: CN14.3 R93.2 U8.A8
WIFI_GPIO_2: CN14.5 R96.2 U8.B11
WIFI_RST: CN14.4 R94.2 U8.A7
WIFI_RX: R92.1 U8.A12
WIFI_TX: R97.2 U8.D12

Pads without a net: CN4 2 5 7; CN5 2 5 7; CN9 7 8 9; CN16 11 12; U2 4 11 14 16 17 19 21 22 29 40 41 42 43 45 46; U4 3 5; U5 9; U6 9; U7 A6 A8 B4 B5 B8 C4 C5 C7 C8 E1 E5 F4 F5 F6 F8 F9 G4 H2 H3 H4 H5; U10 E3 G2 H6; U12 5; U20 17; U22 5

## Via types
v1: diameter 0.508, hole 0.254, TOP to BOTTOM, 231 vias
v2: diameter 0.406, hole 0.203, TOP to BOTTOM, 196 vias
v3: diameter 0.305, hole 0.152, TOP to BOTTOM, 35 vias
v4: diameter 0.61, hole 0.305, TOP to BOTTOM, 389 vias

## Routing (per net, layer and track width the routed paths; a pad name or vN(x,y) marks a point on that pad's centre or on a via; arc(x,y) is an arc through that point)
1V8: length 25.4
  TOP w0.127: U7.D8 v3(14.96,61.1) ; 15.08,56.99 15.12,57.03 U7.D1 ; 16.62,61.97 U7.G9
  TOP w0.229: 15.08,56.99 13.59,55.5 13.59,54.97 C42.1 ; C23.1 17.65,64.64 17.65,63.5 16.62,62.46 16.62,61.97
  TOP w0.508: v4(8.1,55.19) 8.94,56.03 11.86,56.03 12.62,55.27 12.62,55.02 C42.1 ; C57.2 2.71,45.61 ; C57.2 2.1,44.96 ; C57.2 3.32,44.96 ; U9.4 7.24,49.04 ; U9.4 7.24,46.82 ; U9.4 5.38,47.93 ; U9.4 9.09,47.93 ; C23.1 v4(16.89,64.14) ; C20.1 v4(13.46,63.5)
  TOP w1.016: 7.24,43.41 U9.2
  vias: v4(1.83,45.34) v4(1.88,46.13) v4(2.69,46.1) v4(3.45,46.08)
3V3: length 103.1
  TOP w0.127: U7.B2 v3(13.96,57.78) ; U7.D2 14.96,57.78 v3(14.78,57.78) U7.C2 ; 15.62,61.97 U7.E9
  TOP w0.152: C92.1 42.49,65.48 U20.2
  TOP w0.229: C22.1 15.62,64.13 15.62,61.97
  TOP w0.254: U10.D6 46.13,29.27 46.13,27.91 46.61,27.43 46.61,27.1 ; U10.E1 45.6,33.56 45.82,33.78 45.82,34.95 46.48,35.61
  TOP w0.457: R44.1 33.27,55.73 v4(33.43,55.88) ; R45.1 34.54,55.12 v4(34.54,55.75)
  TOP w0.508: R73.2 v4(61.59,12.95) ; v4(48.72,25.45) 48.72,24.74 48.26,24.28 R100.2 48.39,23.5 R63.2 ; v4(25.02,42.93) 25.15,42.8 R55.1 ; v4(21.79,54.74) R41.1 ; C41.1 11.86,54.79 v4(11.4,55.24) ; v4(48.26,46.52) 48.22,46.48 R52.1 ; R82.2 v4(40.79,3.81) ; v4(5.72,63.88) 5.72,64.63 5.71,64.64 ; C22.1 v4(16.76,65.28) ; R43.1 32.13,55.73 v4(32.05,55.8) ; R80.1 v4(39.62,7.49) ; v4(23.75,38.46) 23.75,38.48 24.26,38.99 R59.2 ; C16.2 61.44,67.18 ; C16.2 60.48,67.18 ; C16.2 60.96,66.7 ; v1(45.33,37.74) 45.36,37.74 45.36,37.77 45.54,37.59 C63.2 46.48,35.61 ; v4(26.42,40.64) 26.54,40.77 R60.2 ; X3.4 23.62,45.09 C55.2 v1(21.59,45.09) ; 54.28,66.42 JP1.2 ; JP1.2 55.24,65.46 ; JP1.2 56.21,66.42 ; R27.2 58.59,66.92 ; R27.2 57.78,66.09 ; R27.2 56.98,66.92 ; U9.3 10.25,41.63 ; U9.3 9.54,42.74 ; U9.3 8.83,41.63 ; U9.3 9.54,40.52 ; v4(47.55,25.41) 47.16,25.02 C71.2 46.61,27.1 ; v4(35.18,72.19) U5.8 ; 61.99,67.14 U4.4 62.42,66.59 ; R102.2 v4(41.66,67.01) ; R42.1 v4(30.99,55.75) ; 59.56,66.41 C15.2 ; C15.2 60.17,67.06 ; C15.2 58.95,67.06 ; v4(42.93,67.01) C92.1 ; C33.1 10.97,57.48 v4(11.4,57.48) ; U6.8 v4(28.16,69.77) ; L2.1 v4(20.95,29.97) ; R71.1 v4(28.57,14.61) ; R84.2 v4(60.1,3.81) ; R79.2 v4(61.59,11.3) ; R81.1 v4(38.73,3.81) ; R83.2 v4(58.19,3.81) ; C35.2 v4(10.54,53.47) ; v4(48.11,41) 48.11,41.5 47.57,42.04 R56.2 ; v4(14.27,52.6) R46.2 ; R57.2 26.7,41.91 v4(26.44,42.17) ; R30.2 v4(36.2,59.65)
  BOTTOM w0.165: 23.24,80.9 23.78,80.36 CN16.9
  BOTTOM w0.254: v4(49.23,13.46) CN17.26
  BOTTOM w0.508: 23.24,80.9 22.1,82.04 19.86,82.04 19.5,81.68 C2.1 19.38,82.14 v4(18.84,82.67) ; SB4.2 25.37,73.79 26.92,73.79 v4(27.3,74.17) ; v4(34.09,67.01) v4(41.66,67.01) v4(42.93,67.01) ; R96.1 v4(4.01,24.84) ; R91.2 74.8,37.59 v4(70.48,37.59) ; R94.1 v4(9.22,24.84) ; R95.1 v4(7.95,24.84) ; v4(72.99,47.71) B1.1 B1.3 ; R93.1 v4(5.41,24.84)
  vias: v4(9.14,40.01) v4(10.03,40.01)
3V3_ST_LINK: length 36.3
  TOP w0.229: C1.1 42.84,82.76 U2.48 ; U2.36 v4(48.84,79.59) ; U2.24 48.34,73.49 v4(48.51,73.66) ; U2.9 v4(42.42,75.59)
  TOP w0.254: U2.1 40.81,79.59 40.51,79.88 v4(40.51,80.26)
  TOP w0.508: C12.2 60.17,72.52 ; C12.2 59.69,73 ; C12.2 59.21,72.52 ; R25.1 38.35,72.8 v4(38.66,73.1) 38.66,73.13 39.19,73.66 R24.2 ; v4(41.78,83.19) 42.04,82.93 C1.1 ; 46.99,83.95 v4(46.99,84.84) ; v4(54.48,60.83) 54.99,60.33 CN9.1 ; U3.5 62.31,72.58 ; U3.5 60.76,72.58 ; U3.5 61.54,73.1 ; U3.5 61.54,72.06 ; LD4.4 v4(35.05,94.72) ; C11.2 58.9,72.77 ; C11.2 57.68,72.77 ; C11.2 58.29,73.42
  L4_SIG w0.508: v4(56.26,72.64) 56.26,70.48 56.64,70.1 56.64,64.64 54.48,62.48 v4(54.48,60.83)
  BOTTOM w0.508: C82.2 42.44,75.56 v4(42.42,75.59) ; v4(48.84,79.59) 49.18,79.25 C81.2 ; C83.2 48.26,73.41 v4(48.51,73.66) ; T3.3 v4(51.82,80.69)
  vias: v4(57.28,73.28) v4(57.28,72.52)
